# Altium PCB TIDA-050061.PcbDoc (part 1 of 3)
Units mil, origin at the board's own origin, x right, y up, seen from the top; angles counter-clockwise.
Board outline 3950.94 x 4411.21 mil, 8 copper layers (Top Layer, Layer 1, Layer 2, Layer 3, Layer 4, Layer 5, Layer 6, Bottom Layer), stack 61.2 mil thick; 178 components, 34 nets, 398 pads, 112 vias.
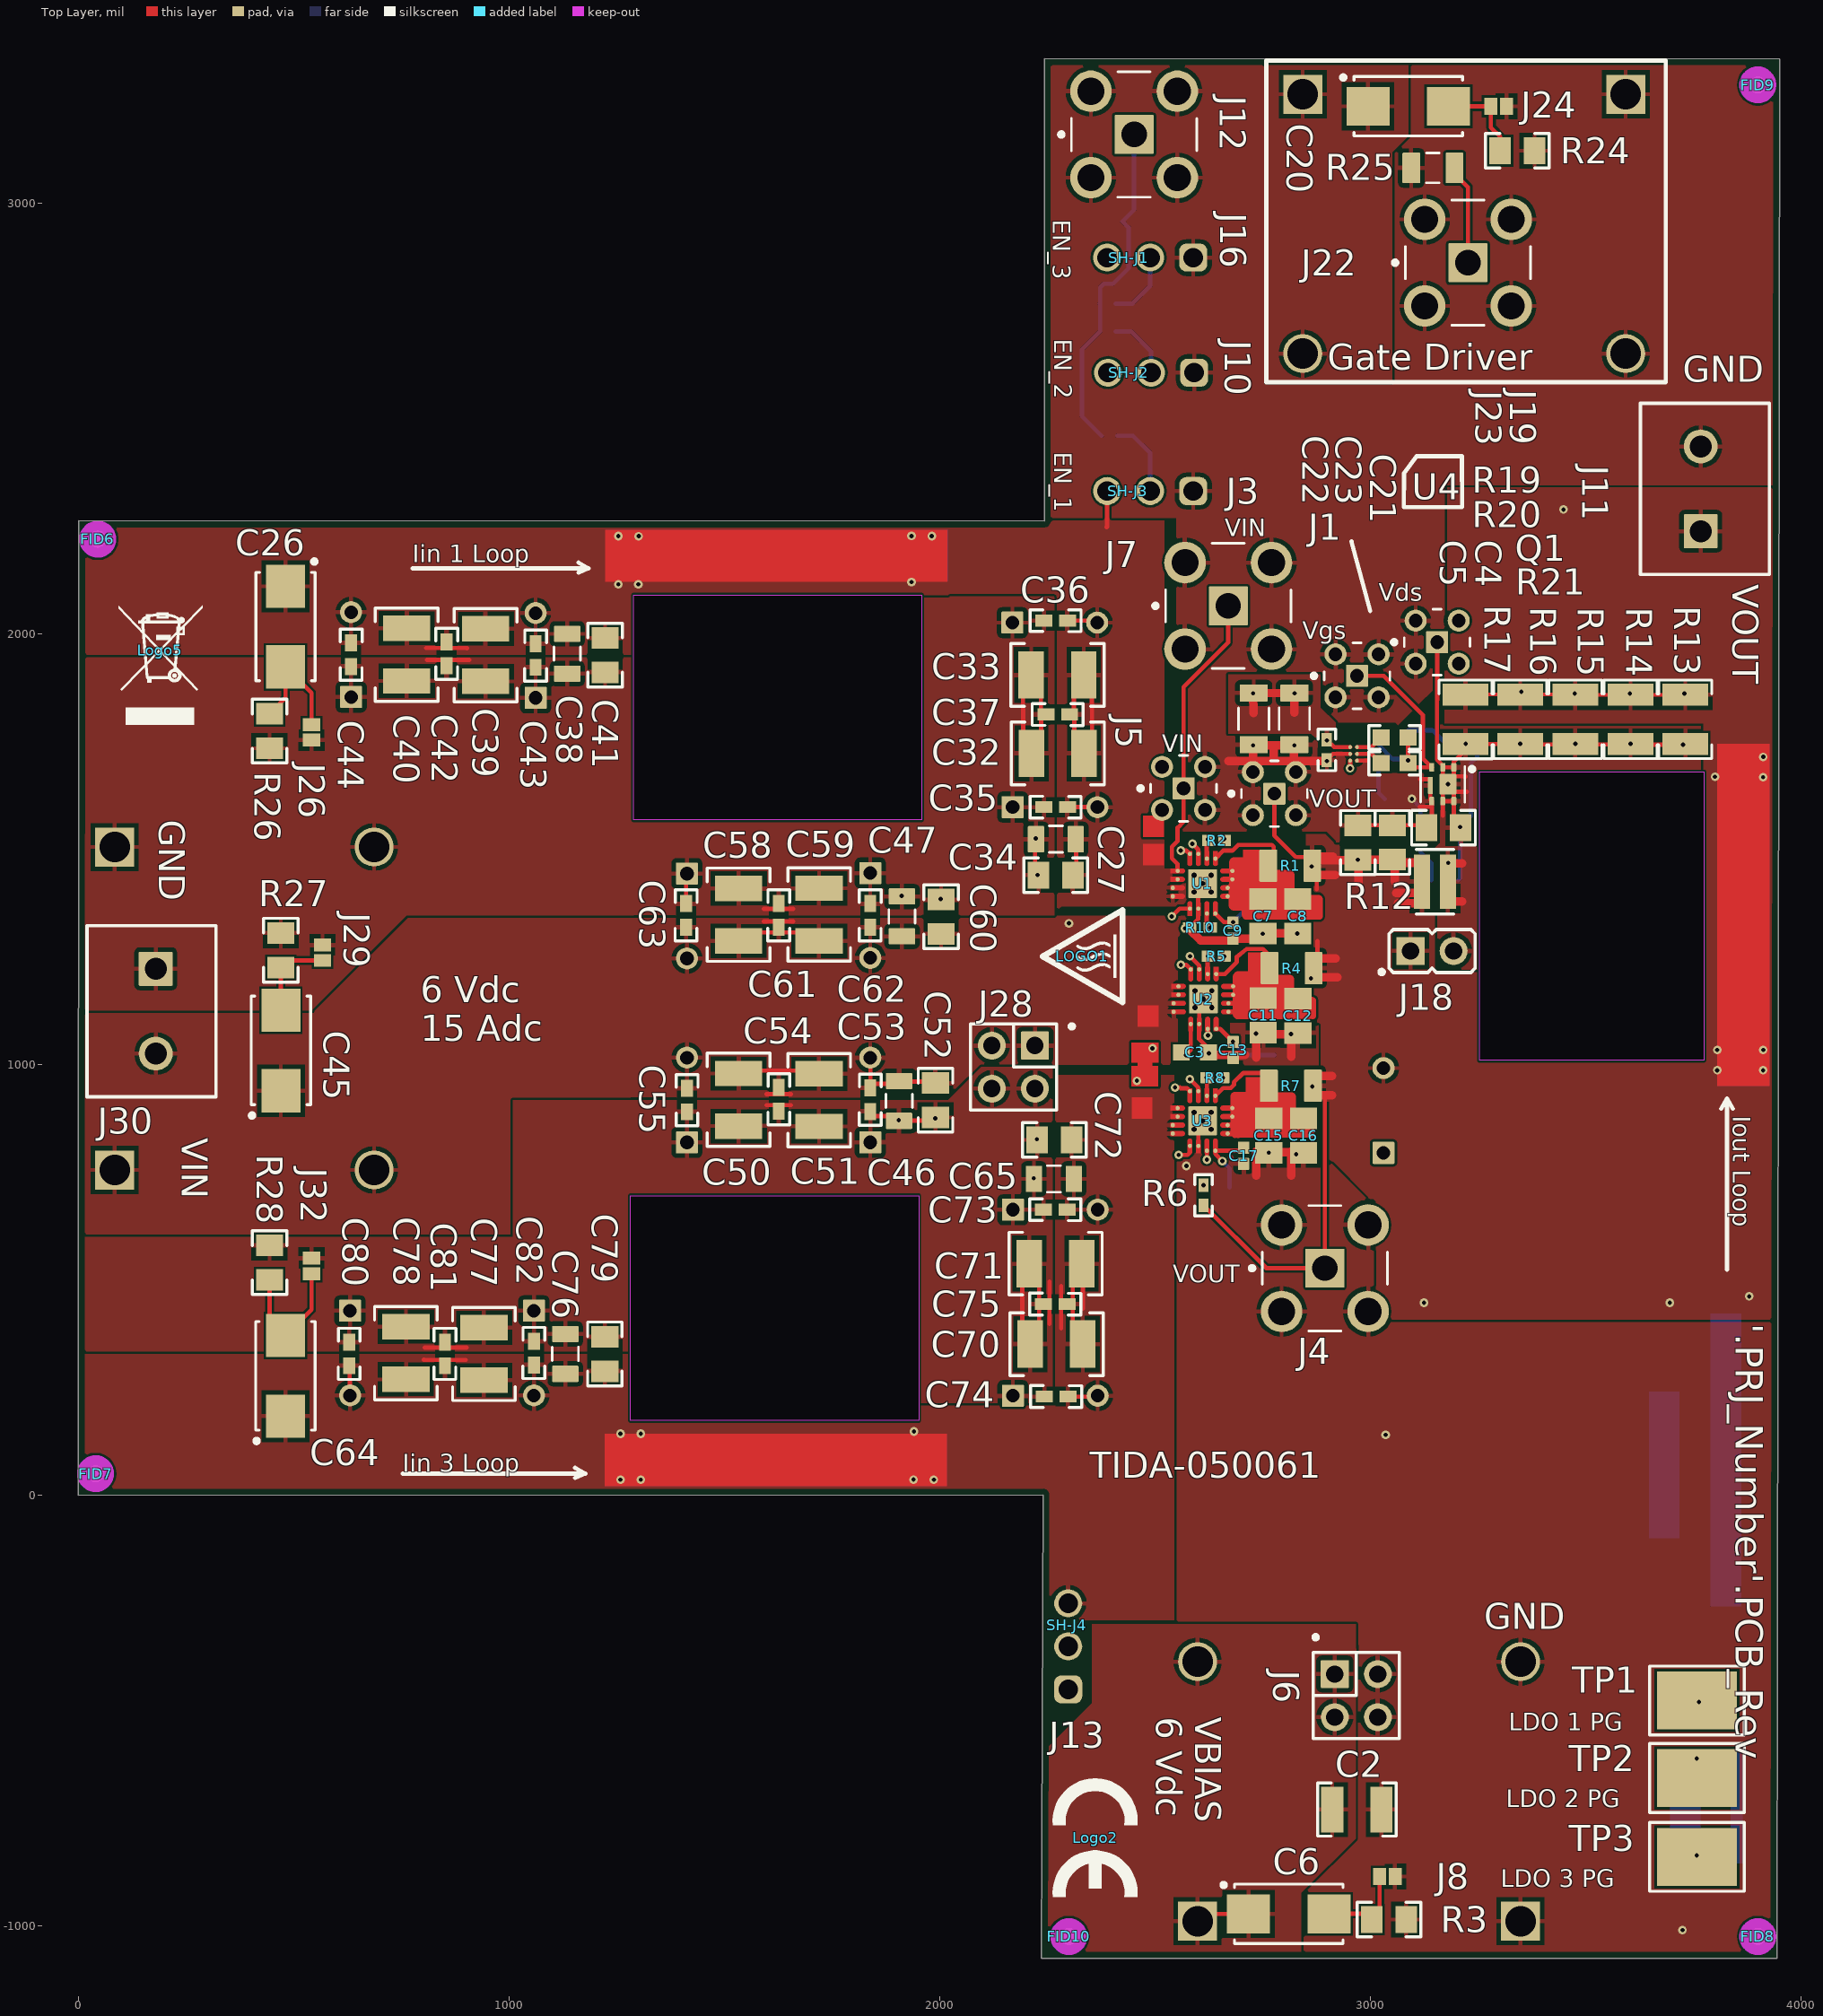
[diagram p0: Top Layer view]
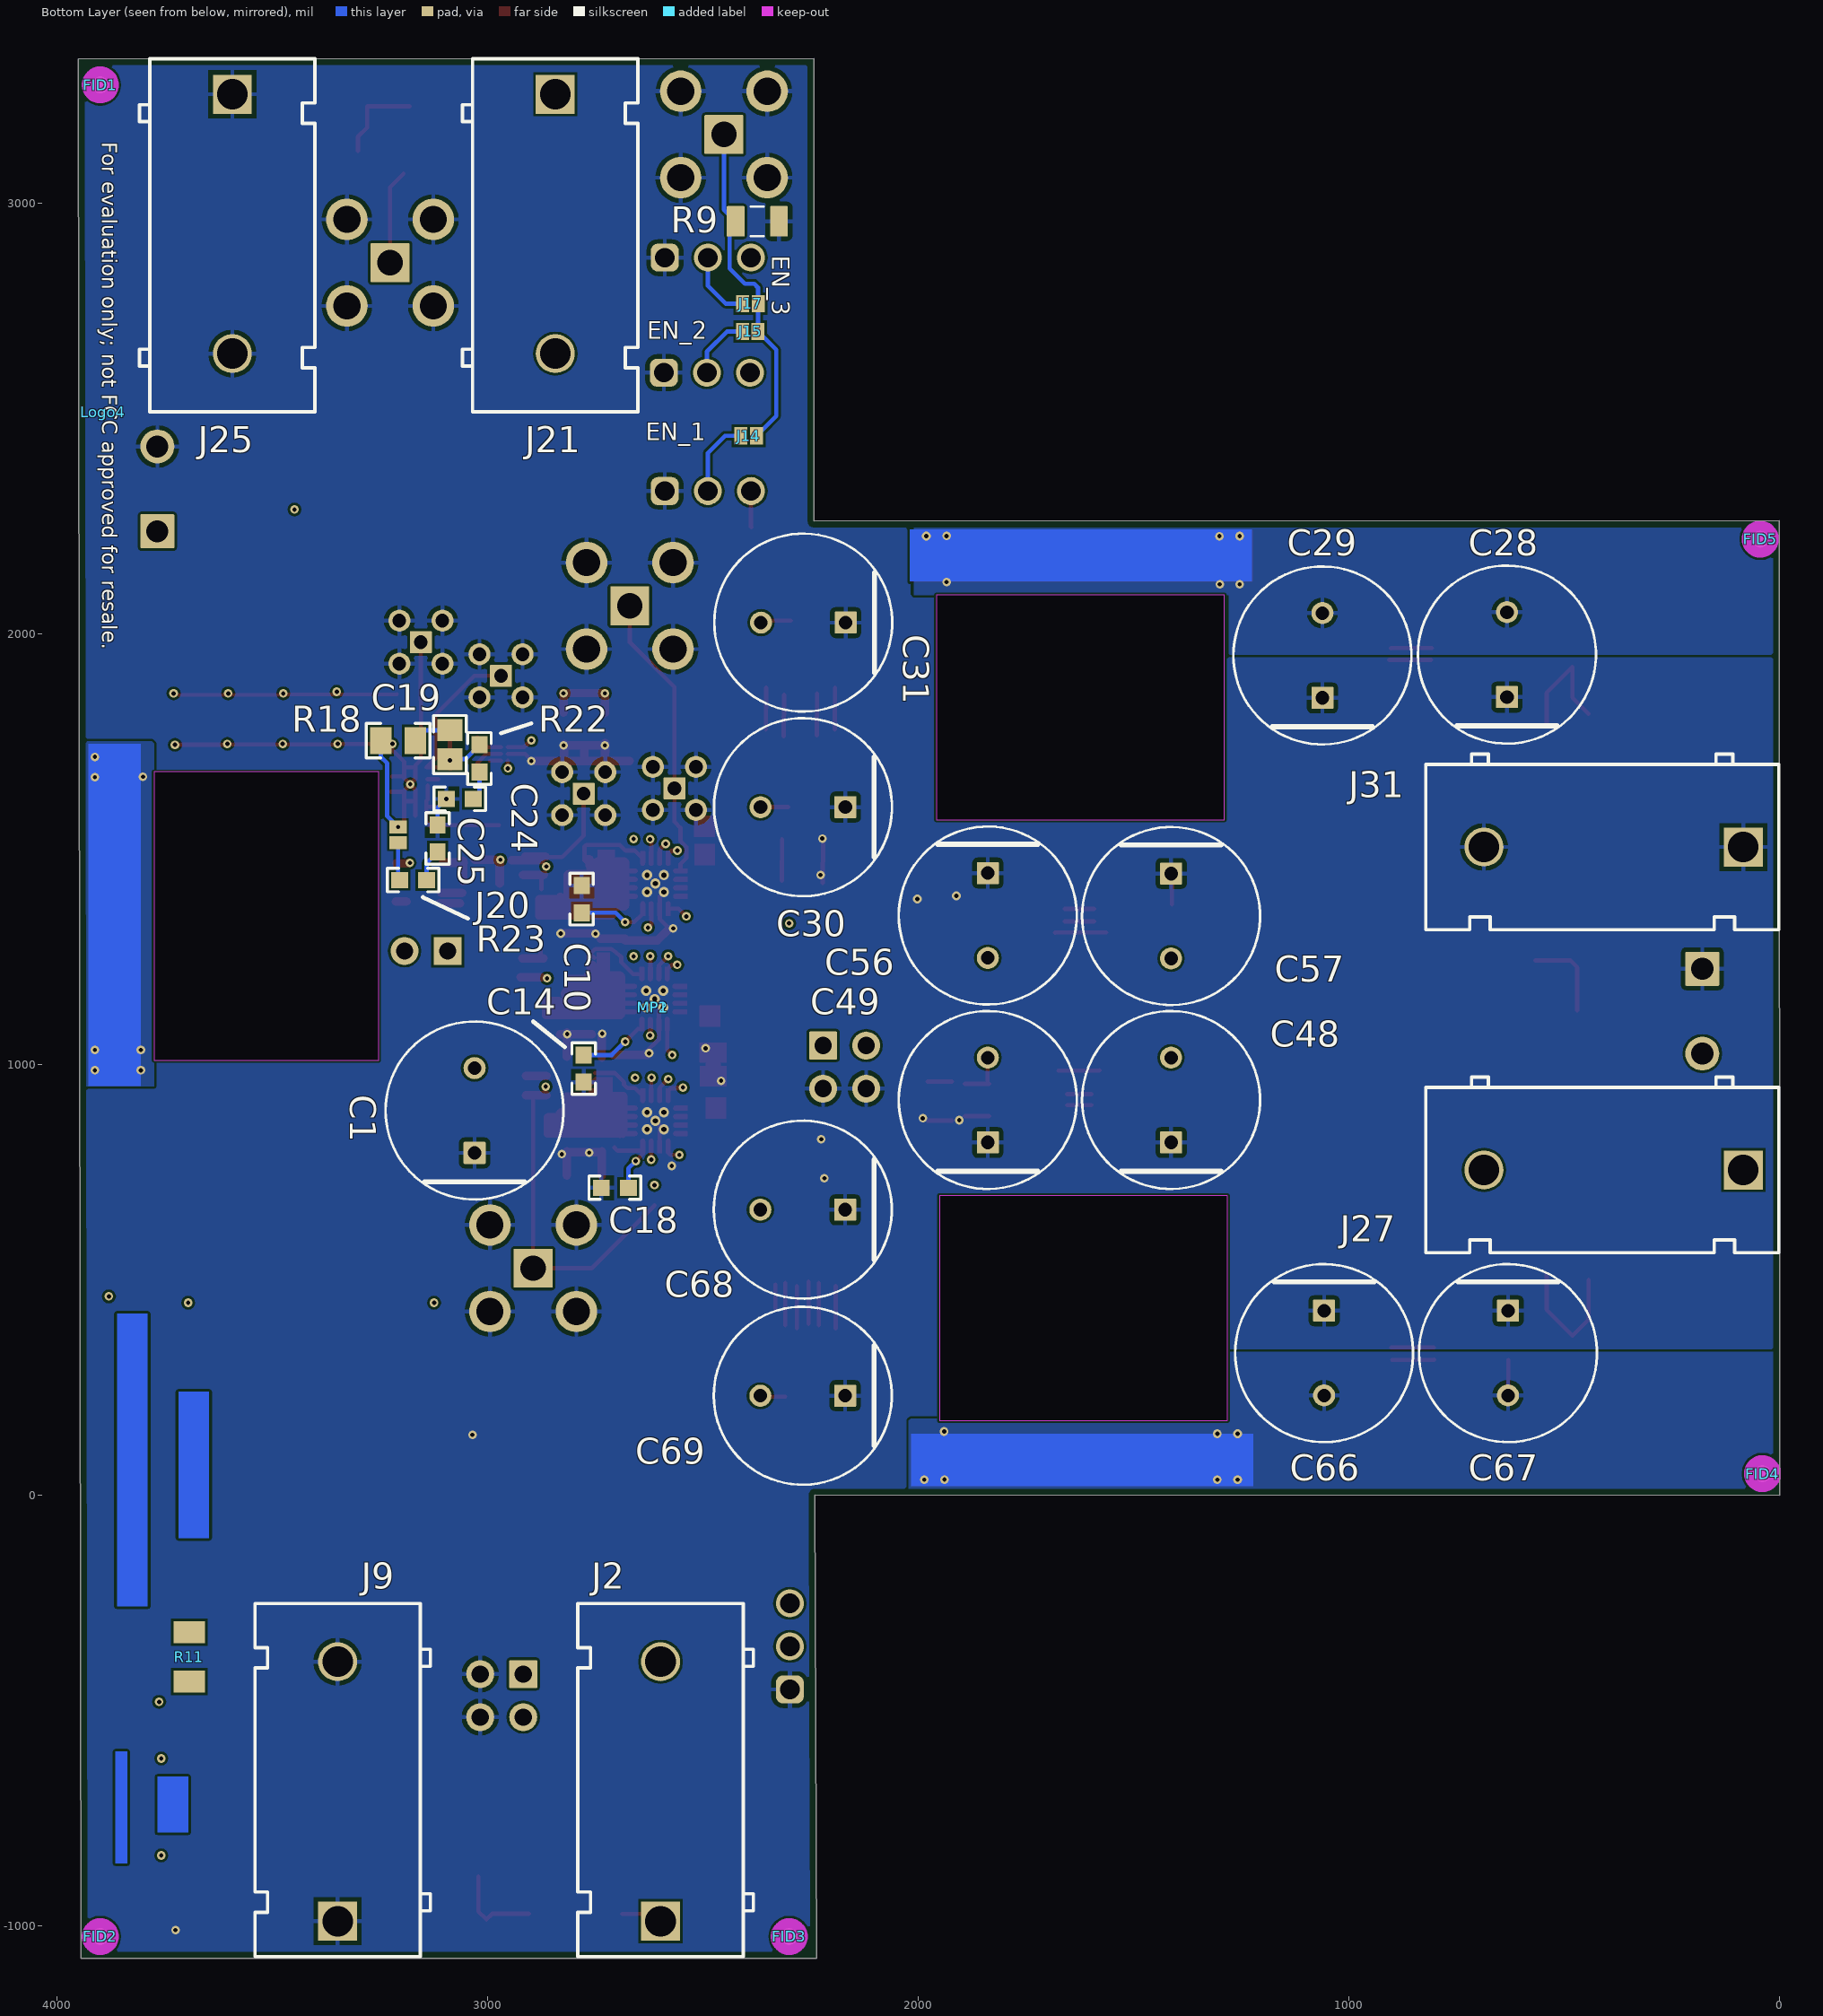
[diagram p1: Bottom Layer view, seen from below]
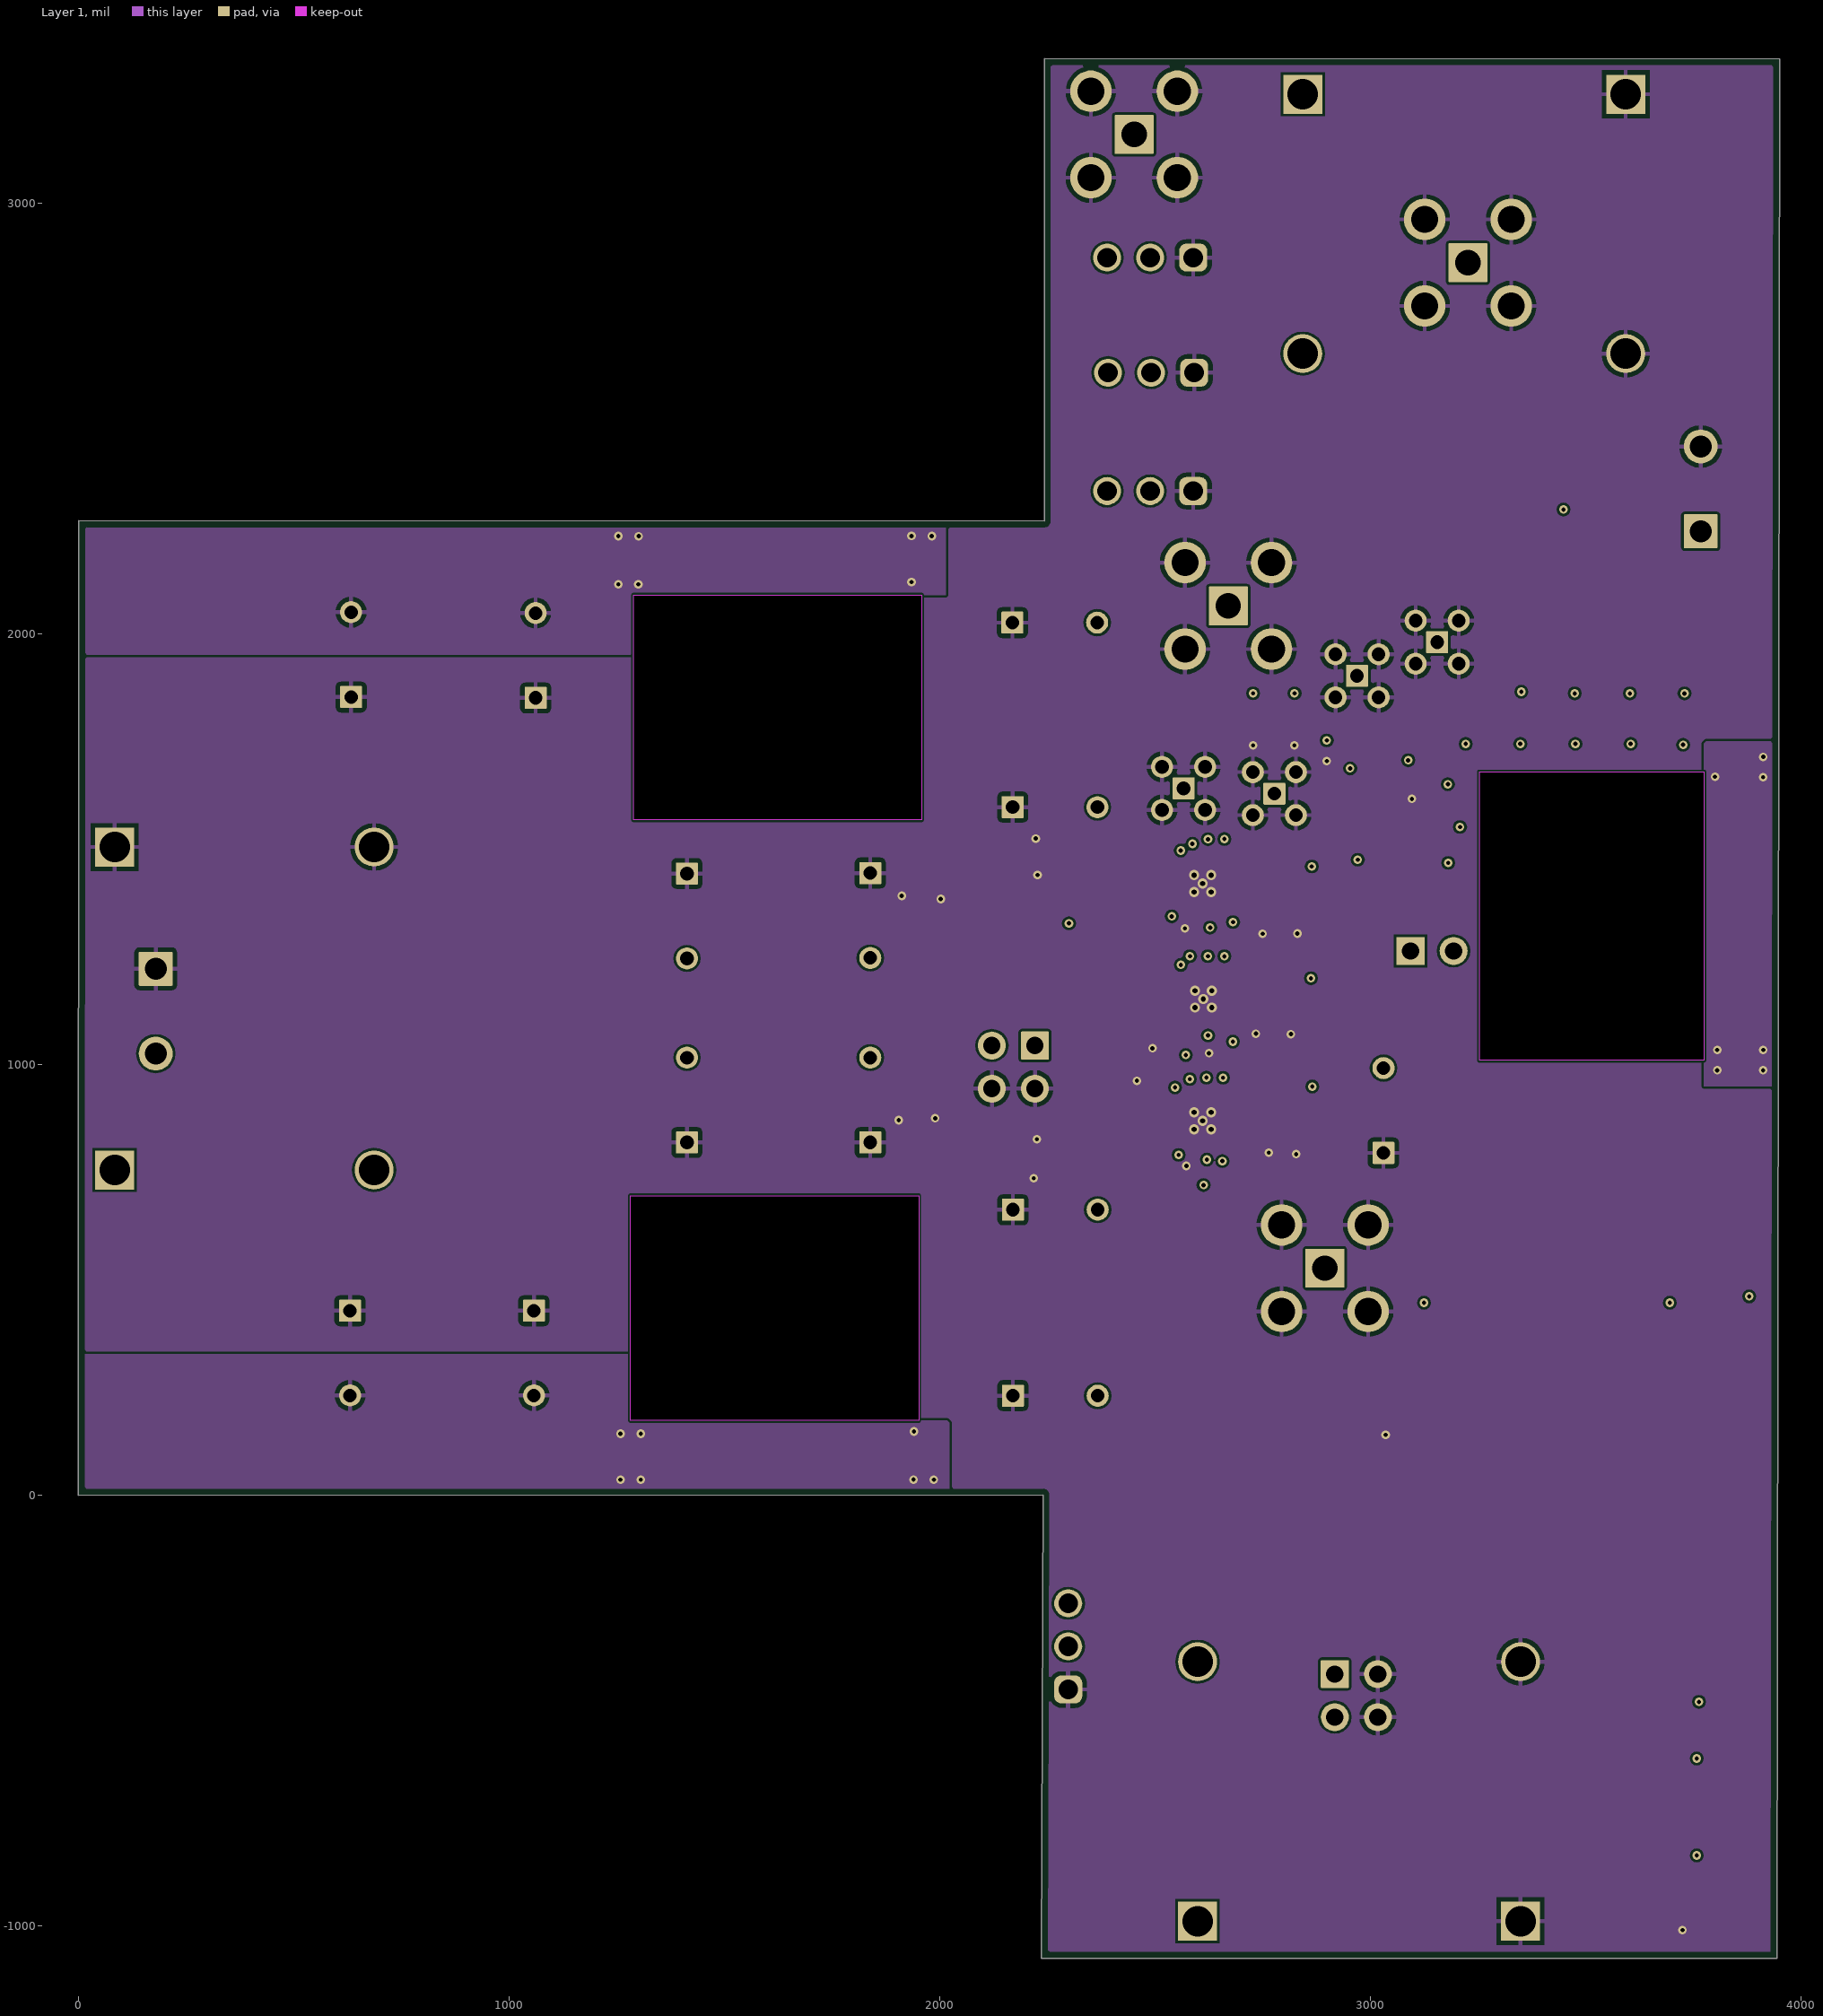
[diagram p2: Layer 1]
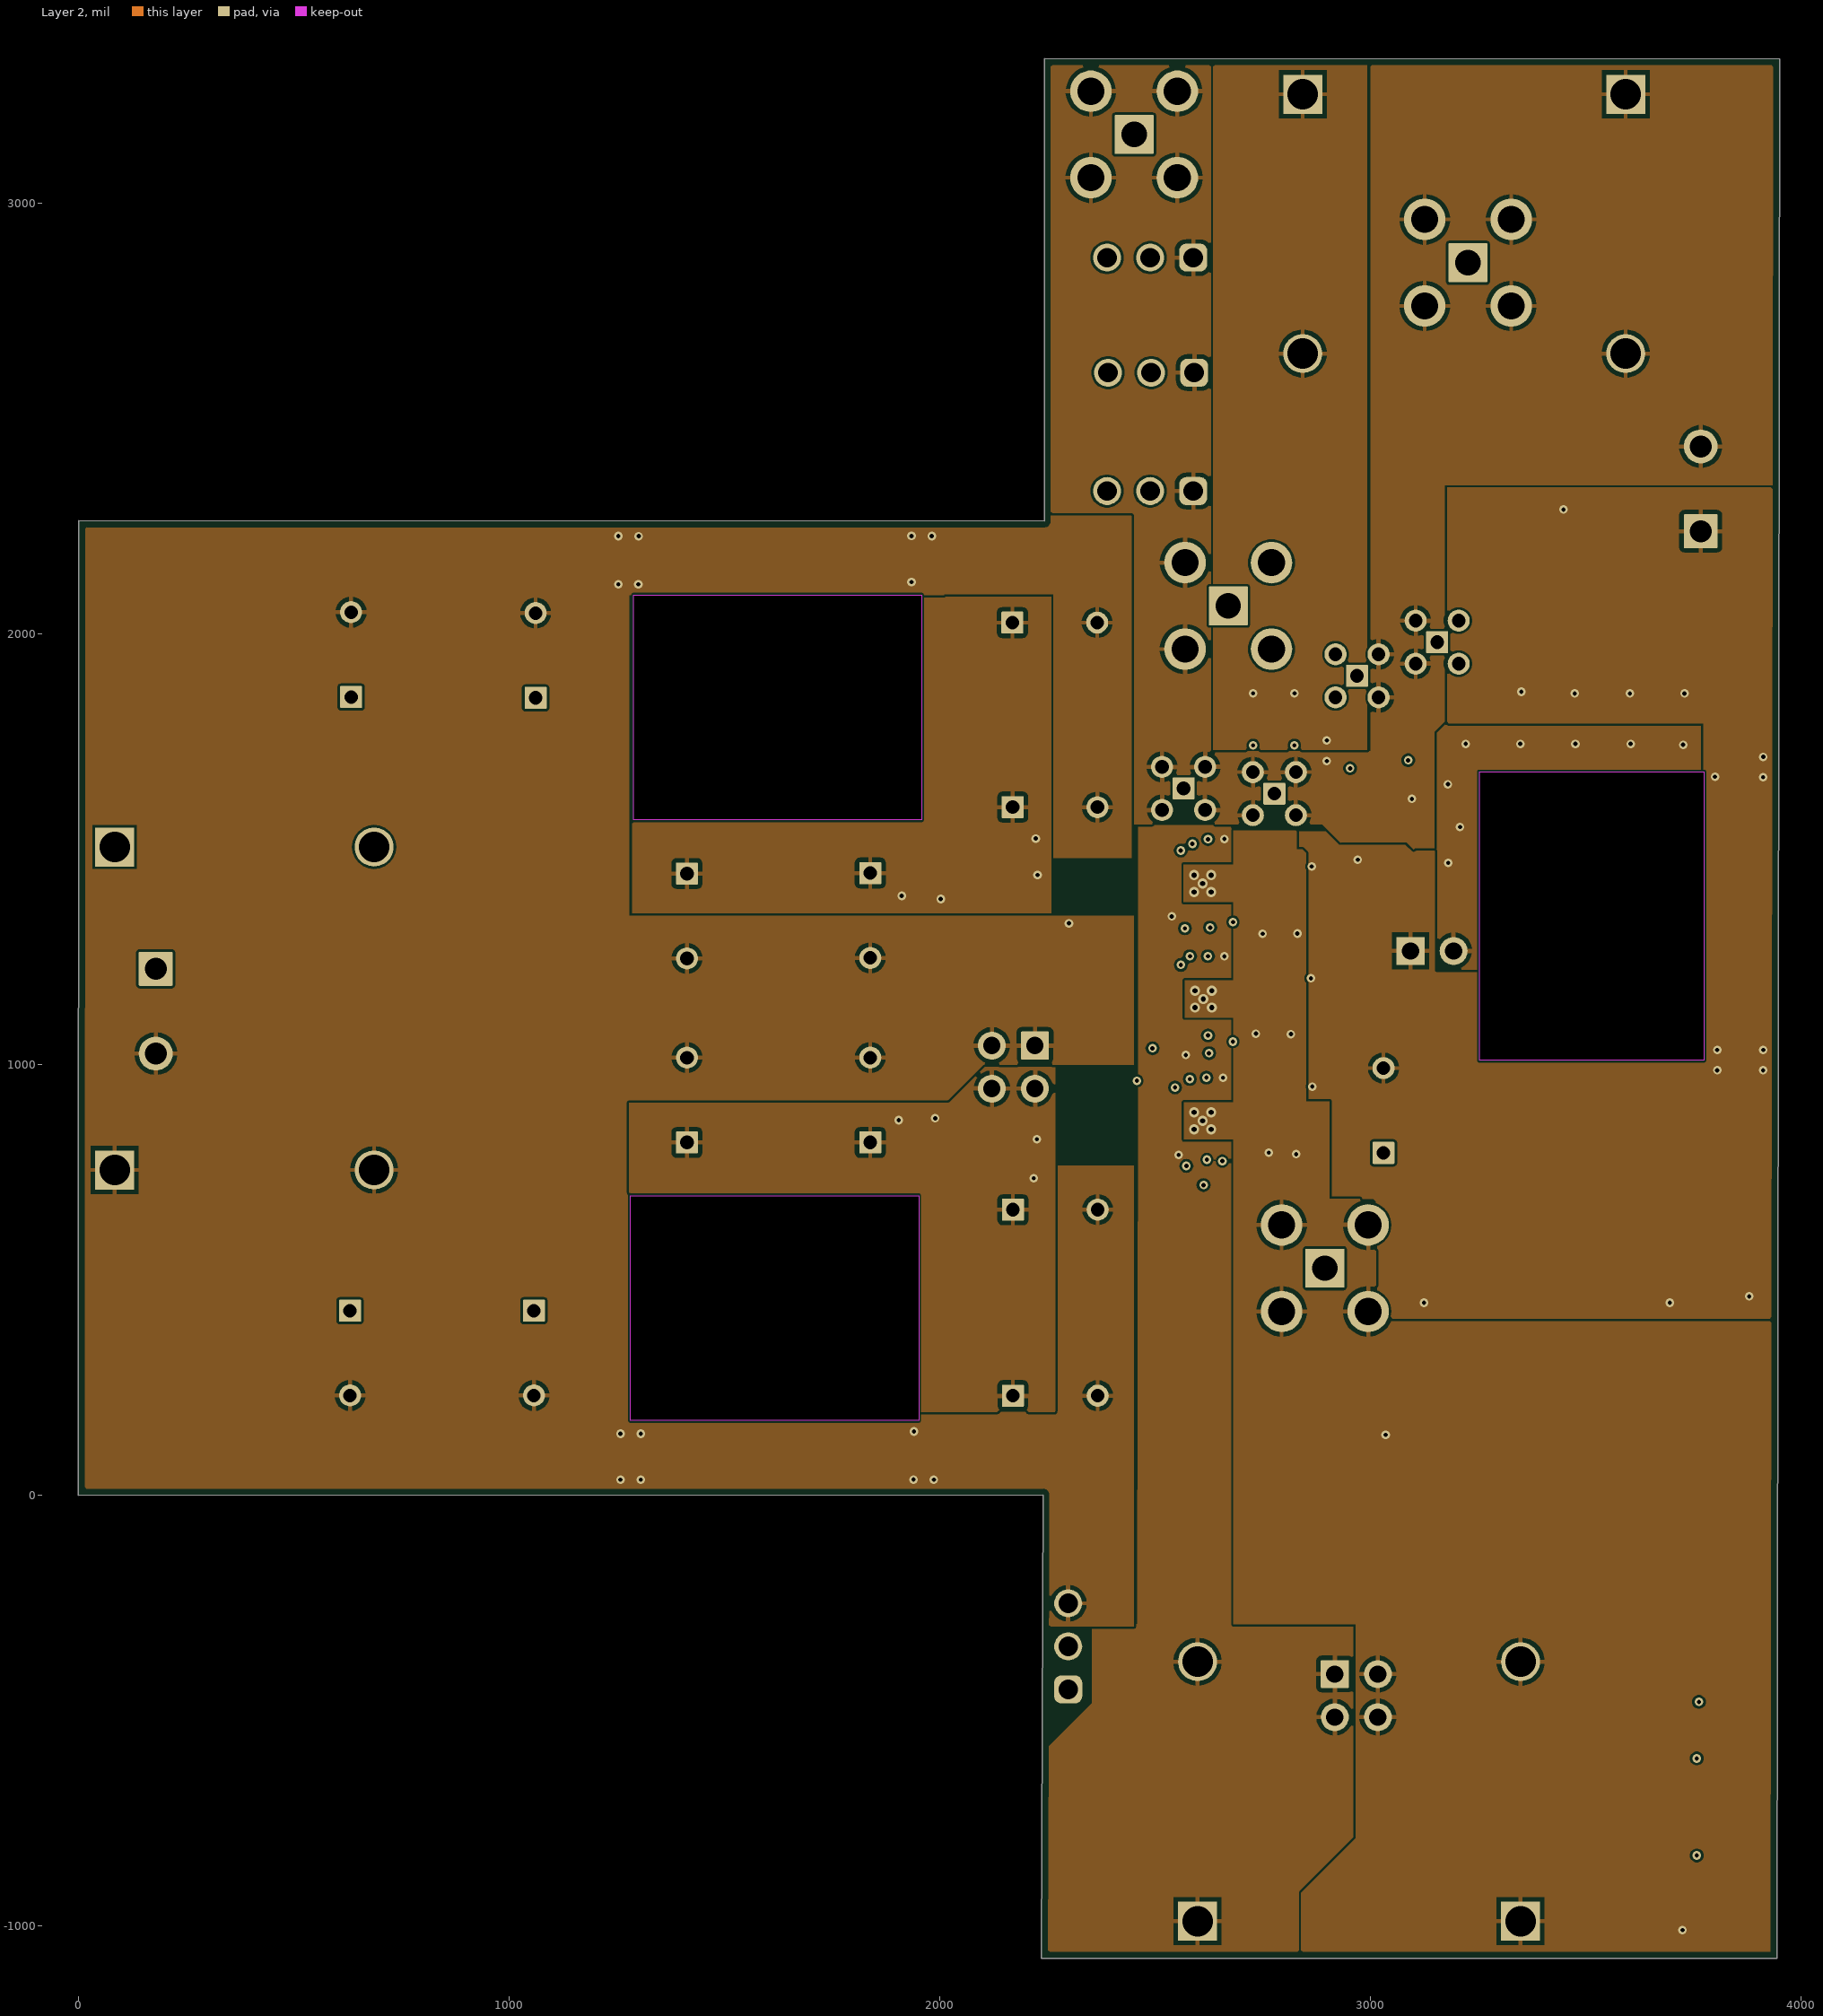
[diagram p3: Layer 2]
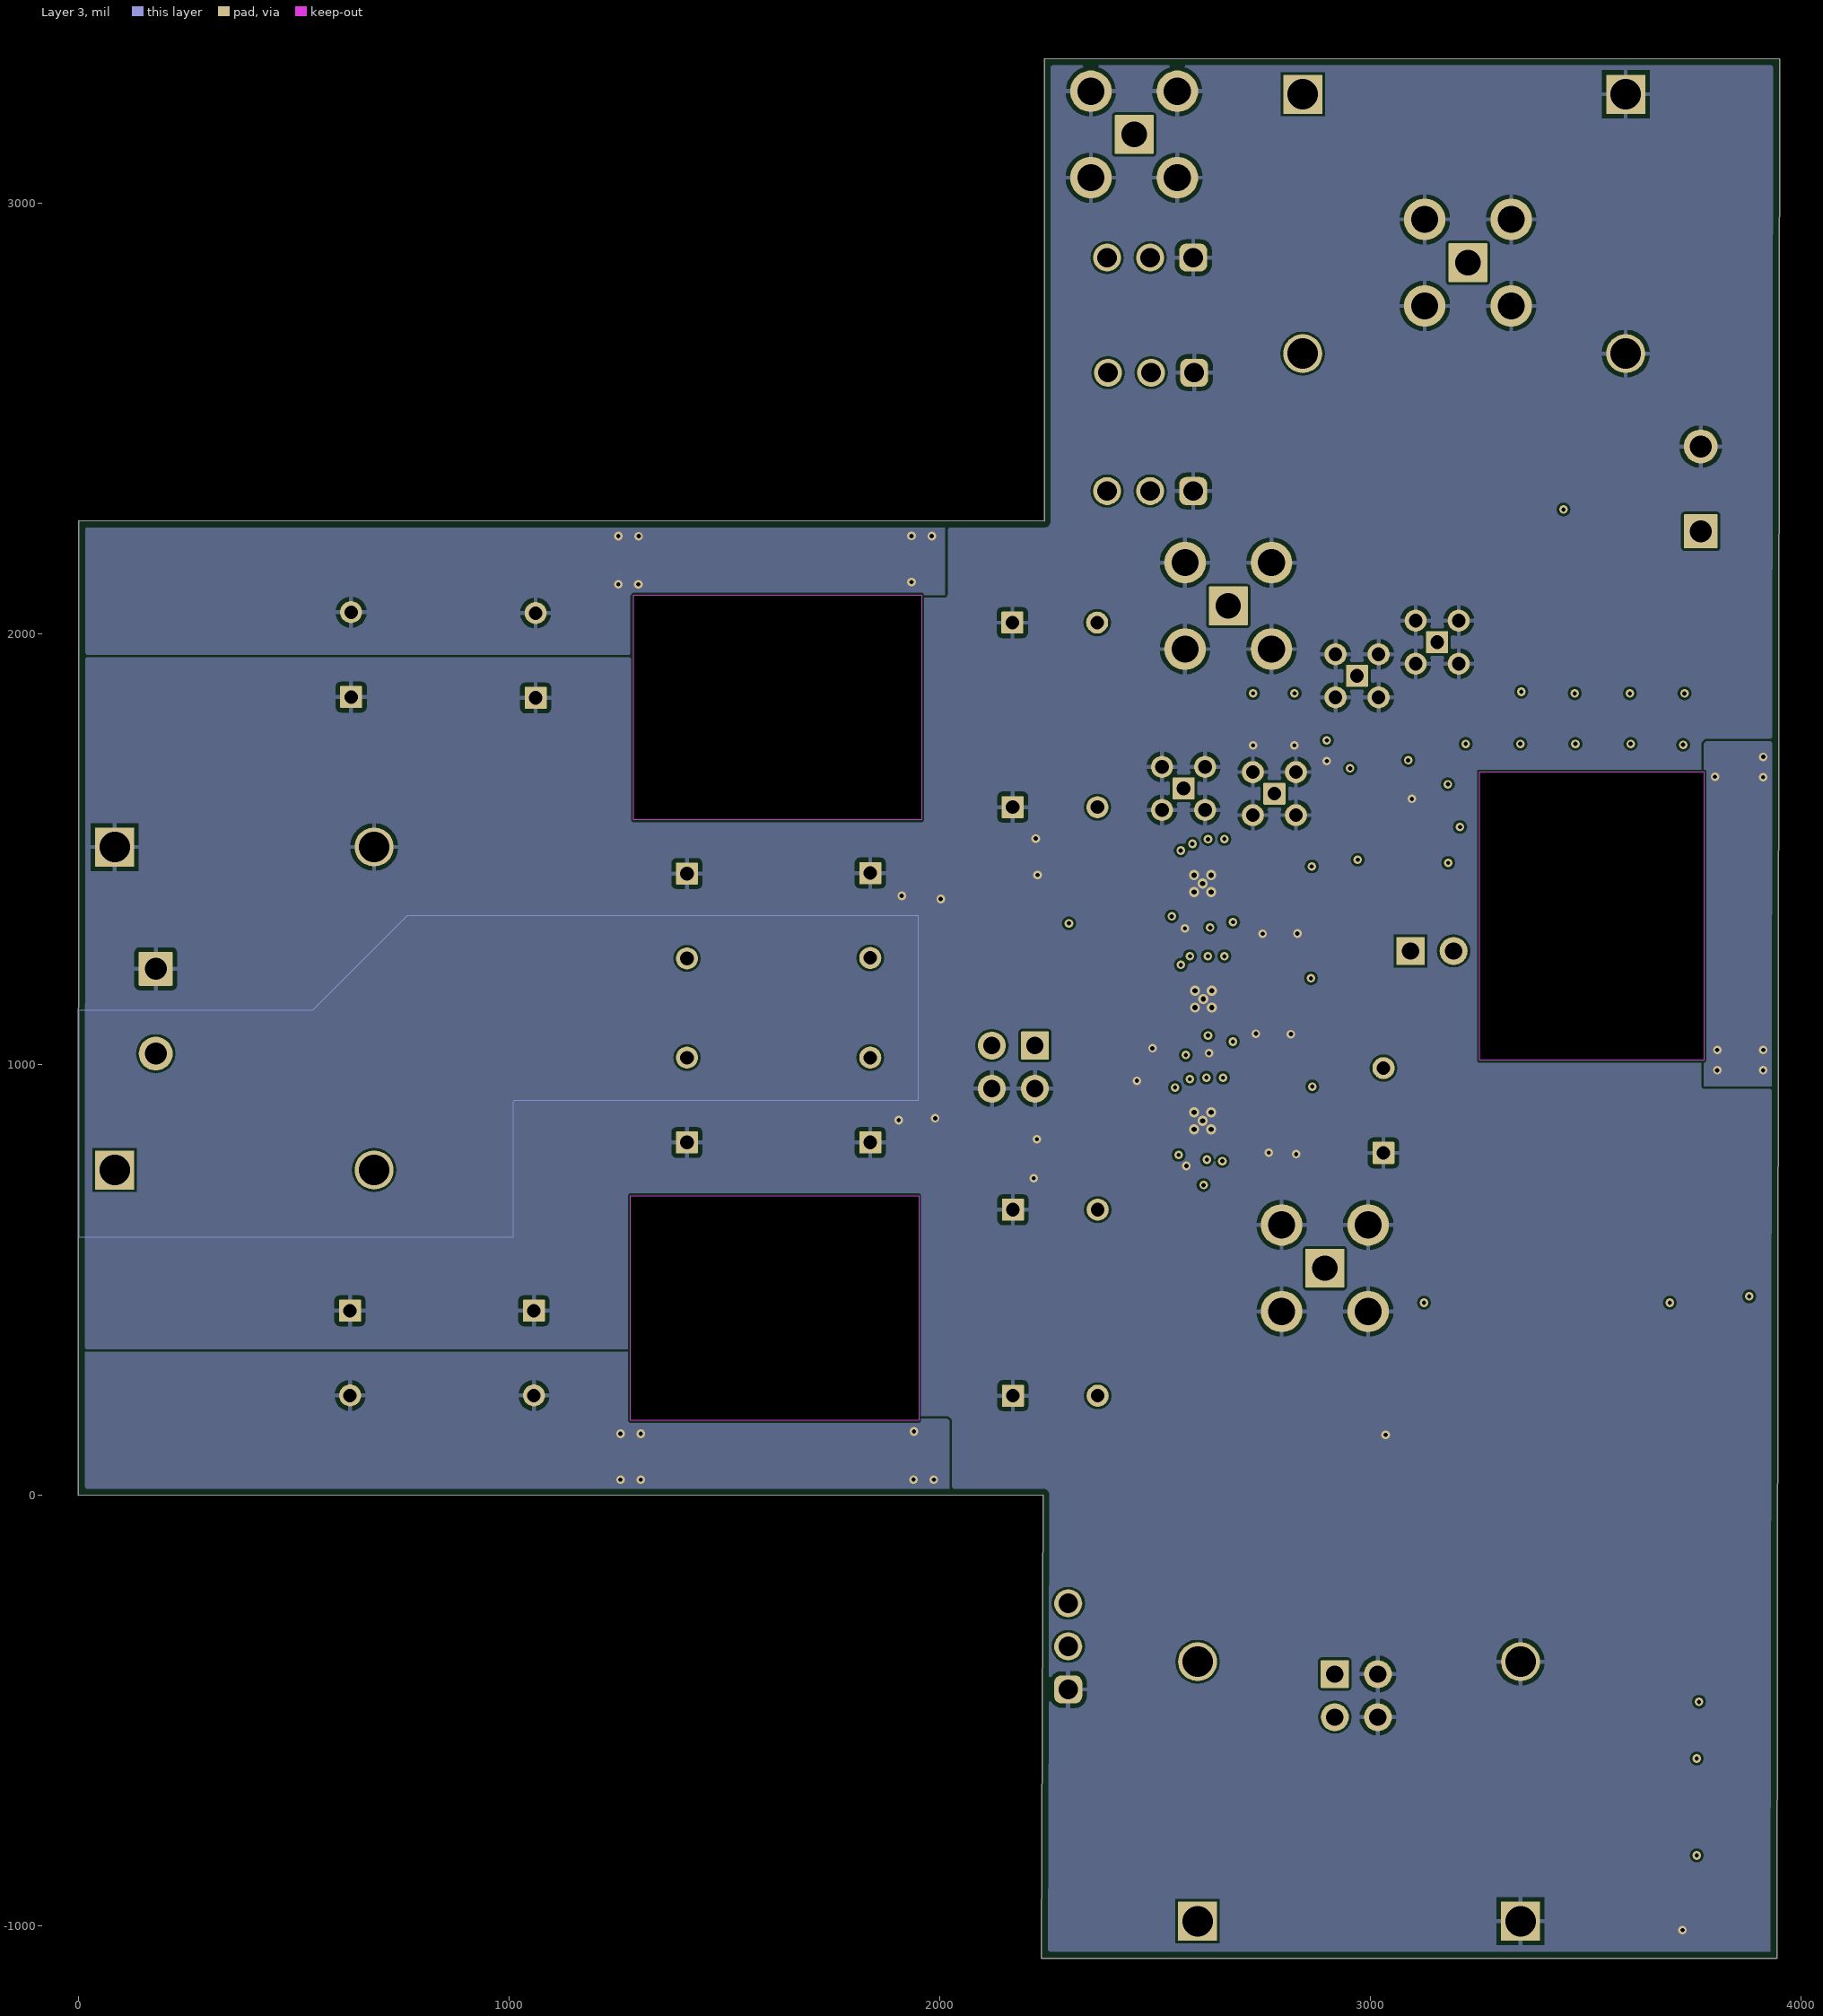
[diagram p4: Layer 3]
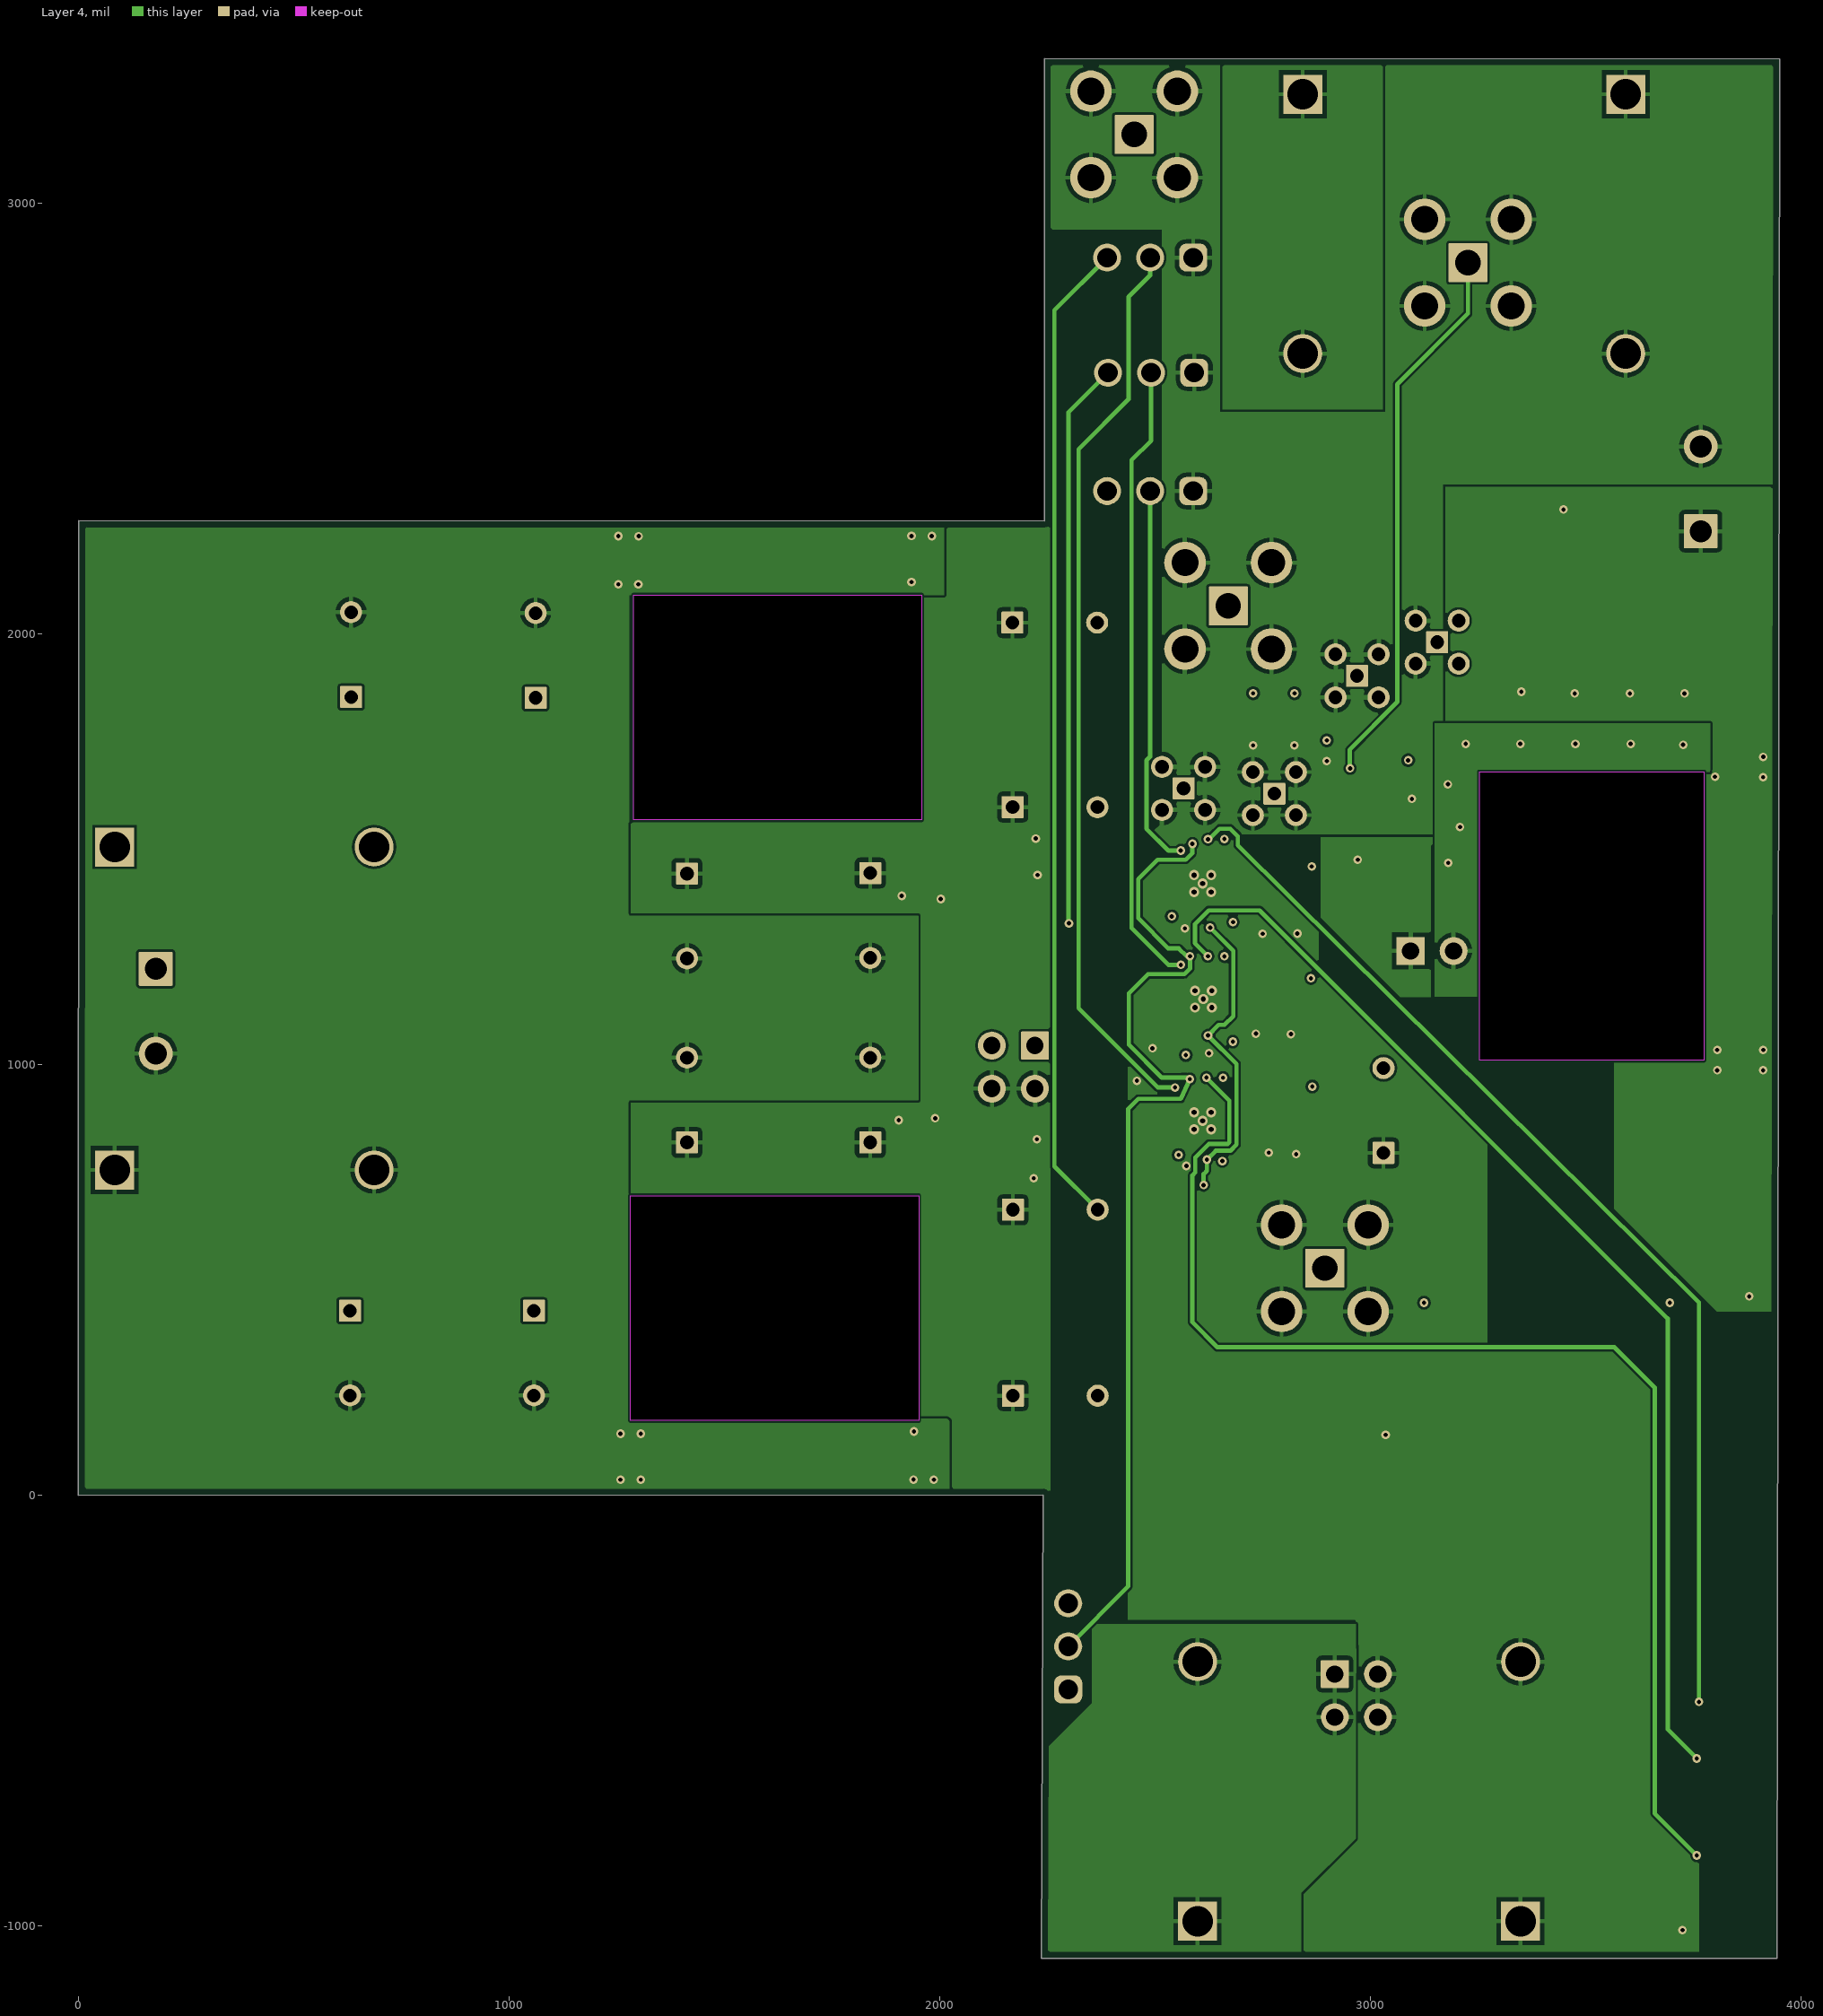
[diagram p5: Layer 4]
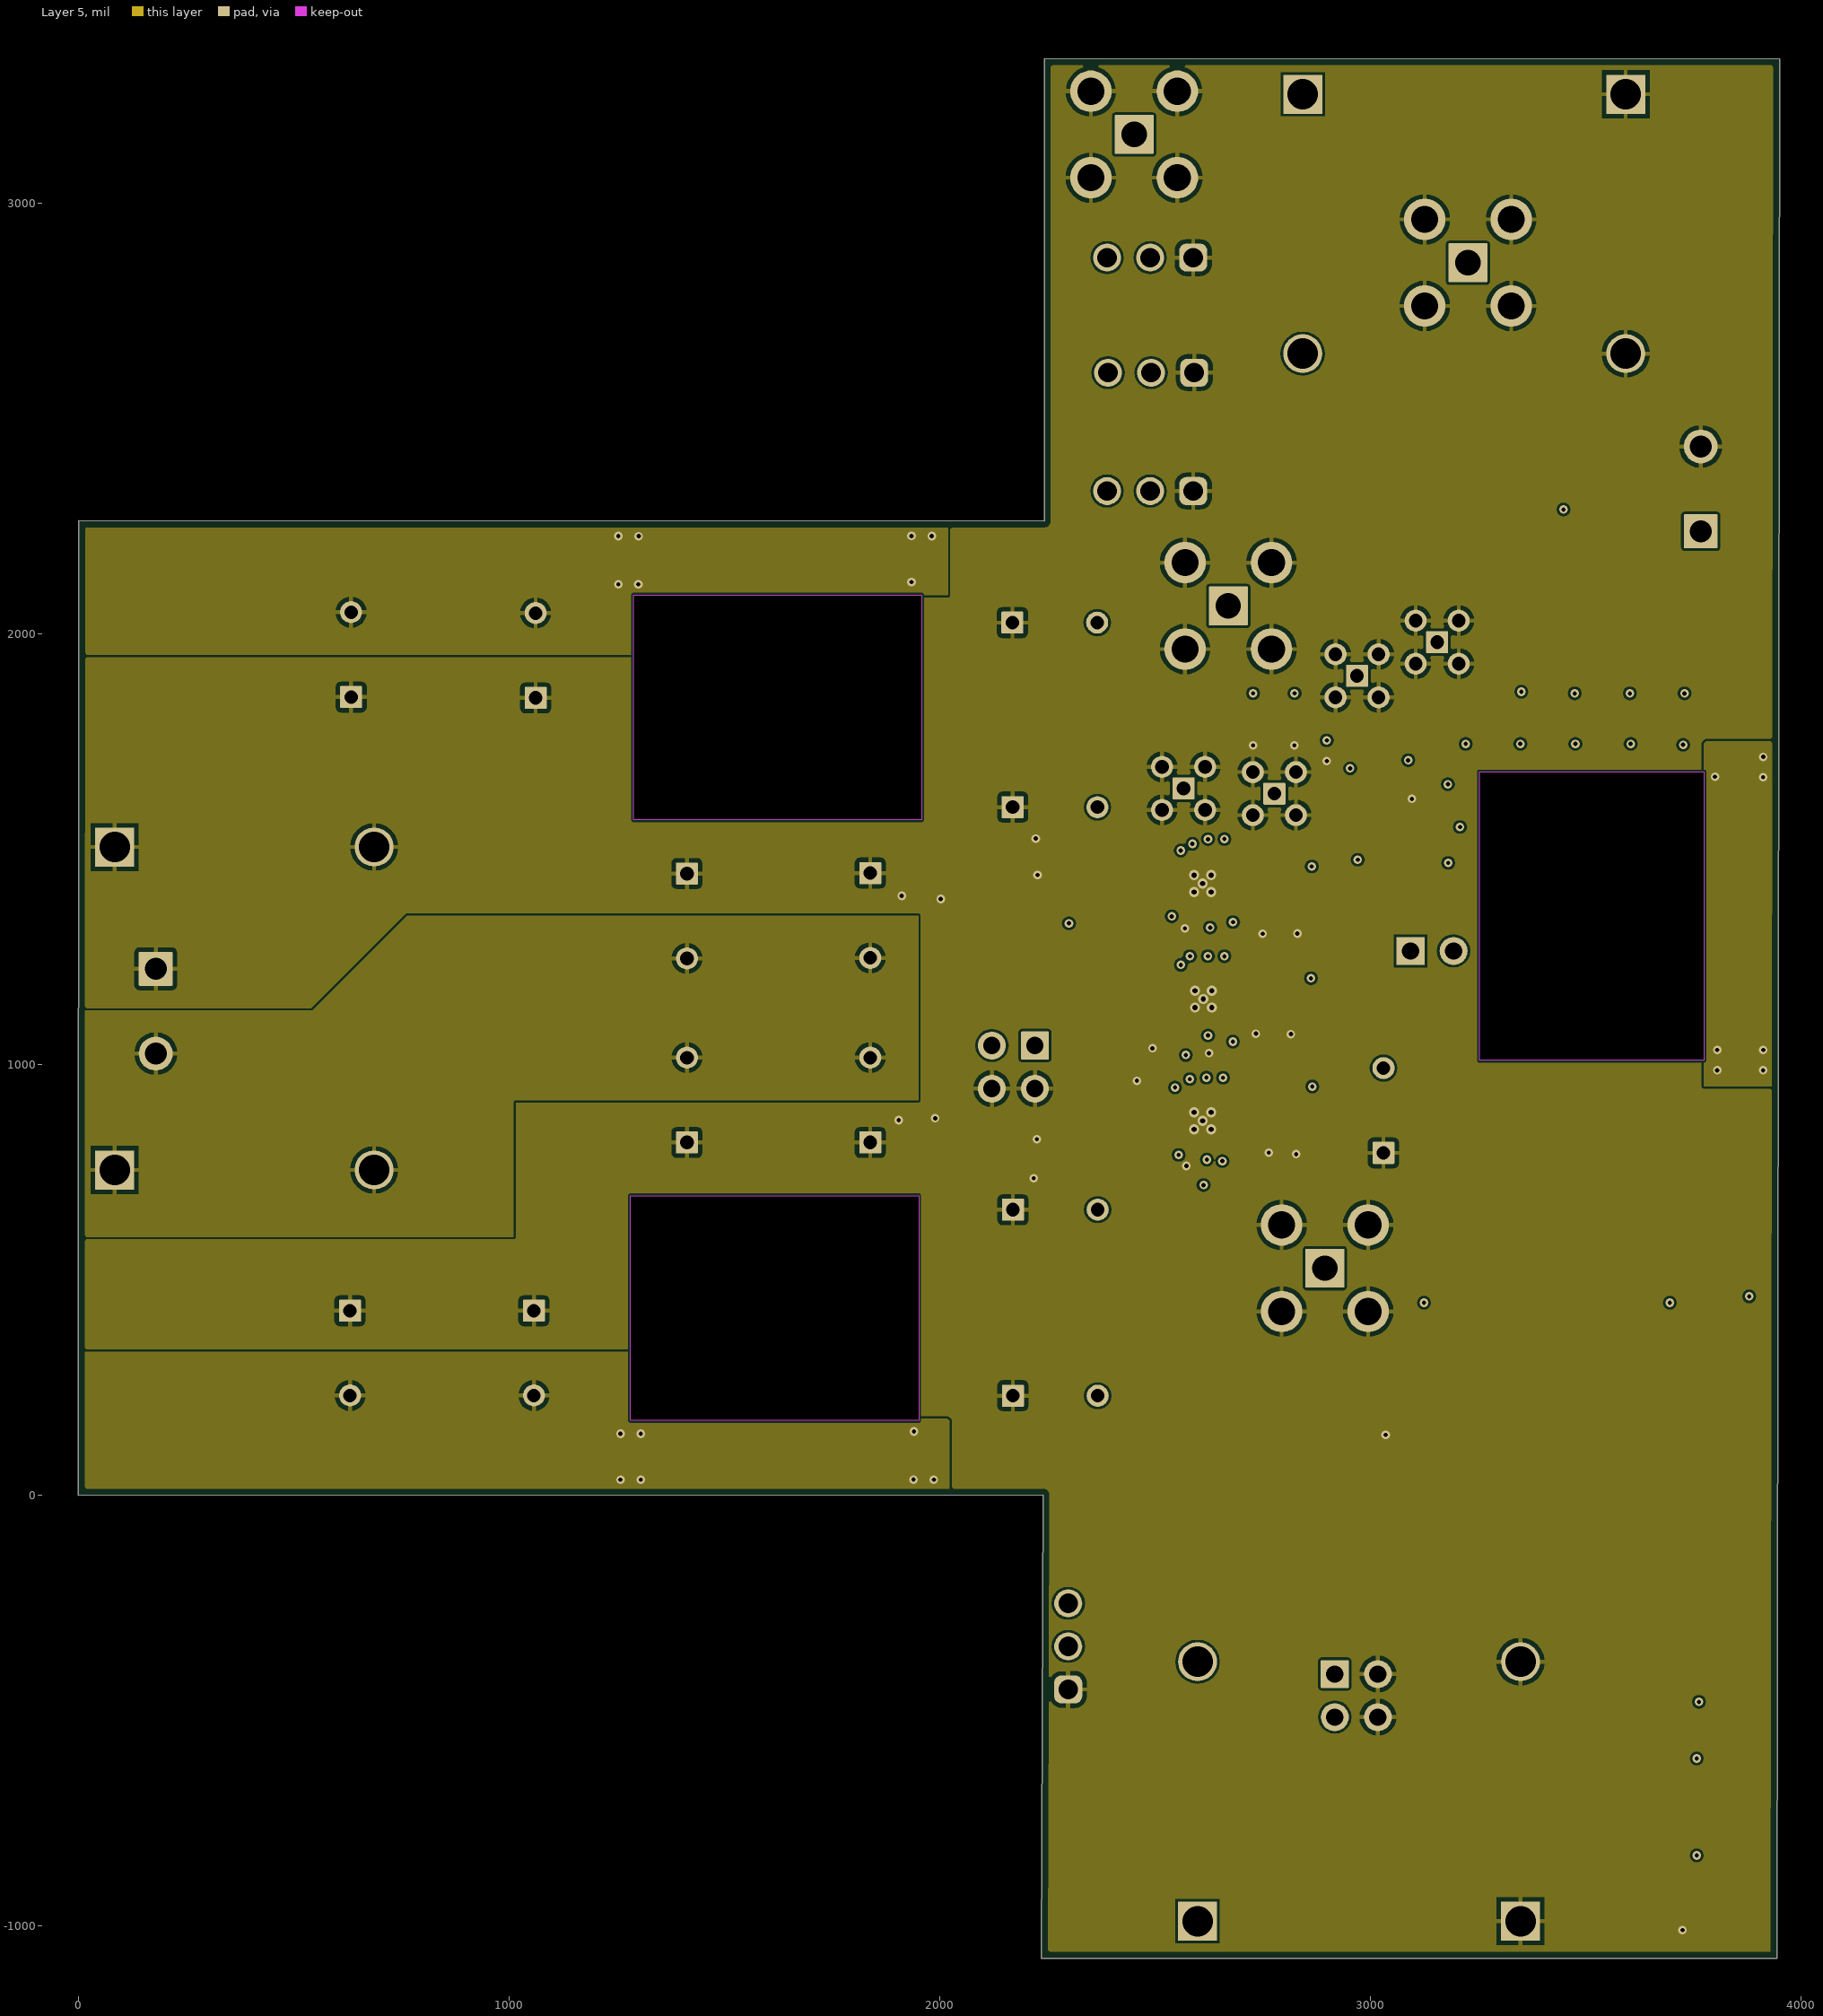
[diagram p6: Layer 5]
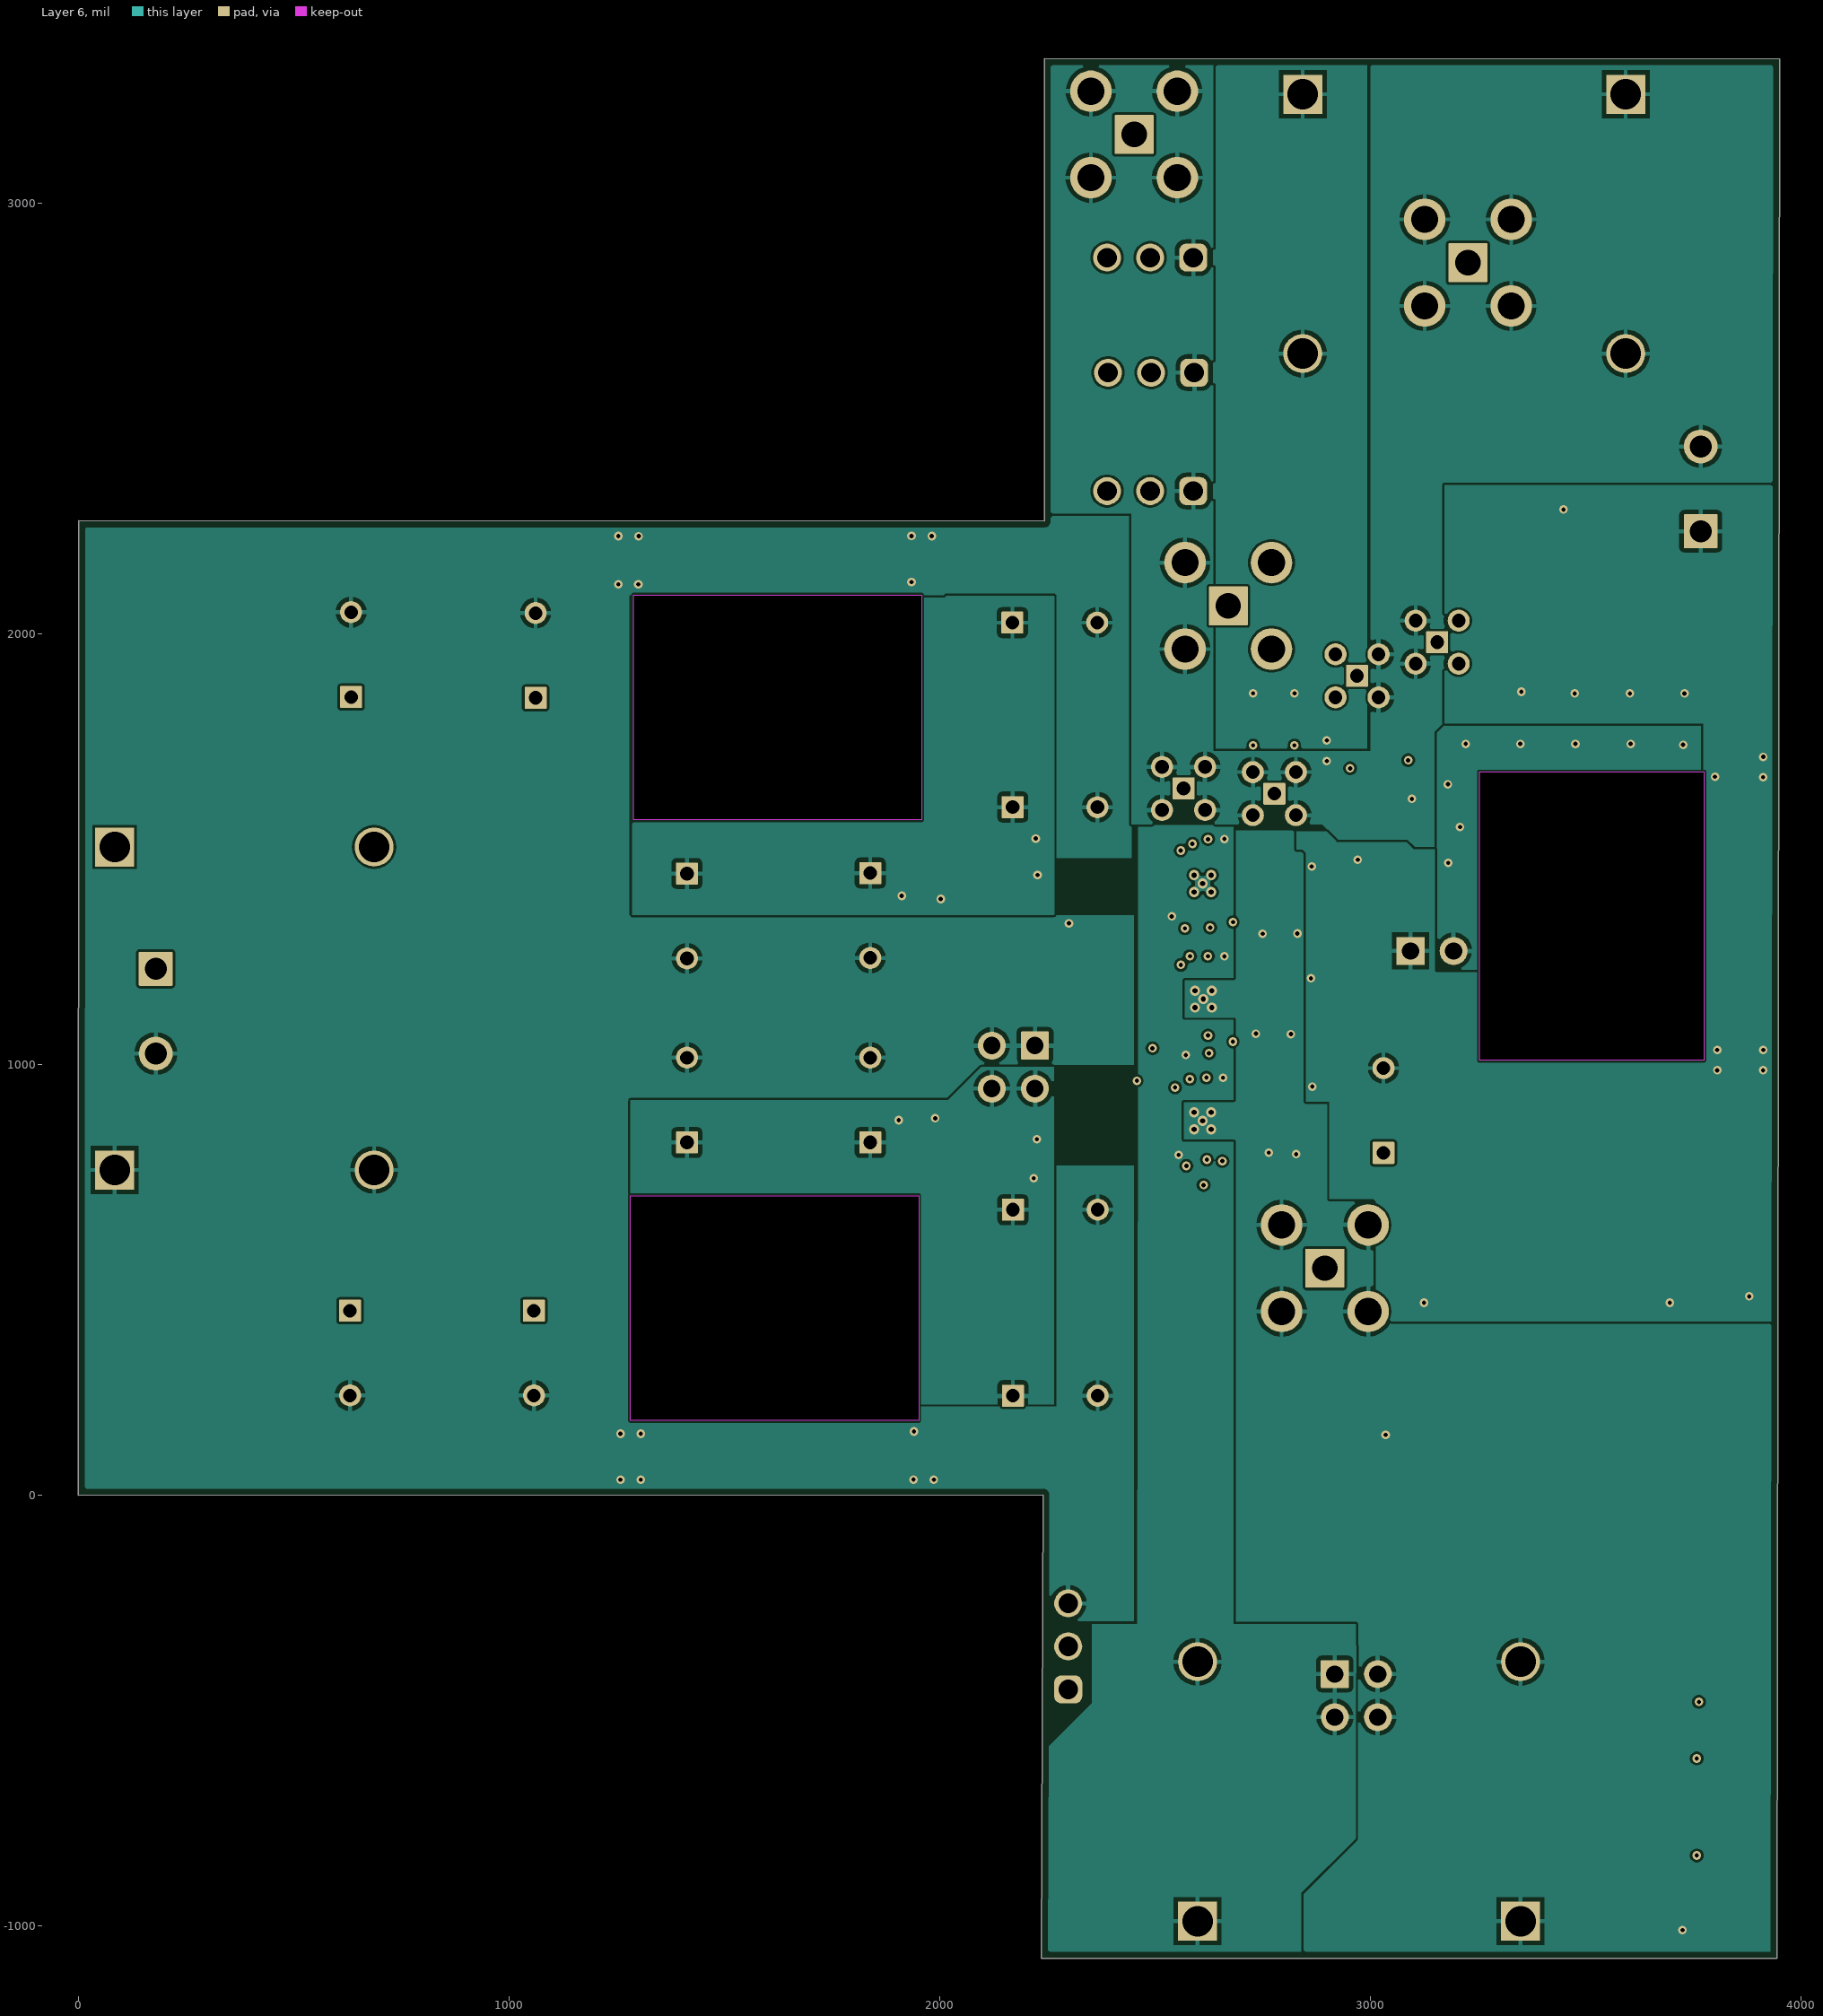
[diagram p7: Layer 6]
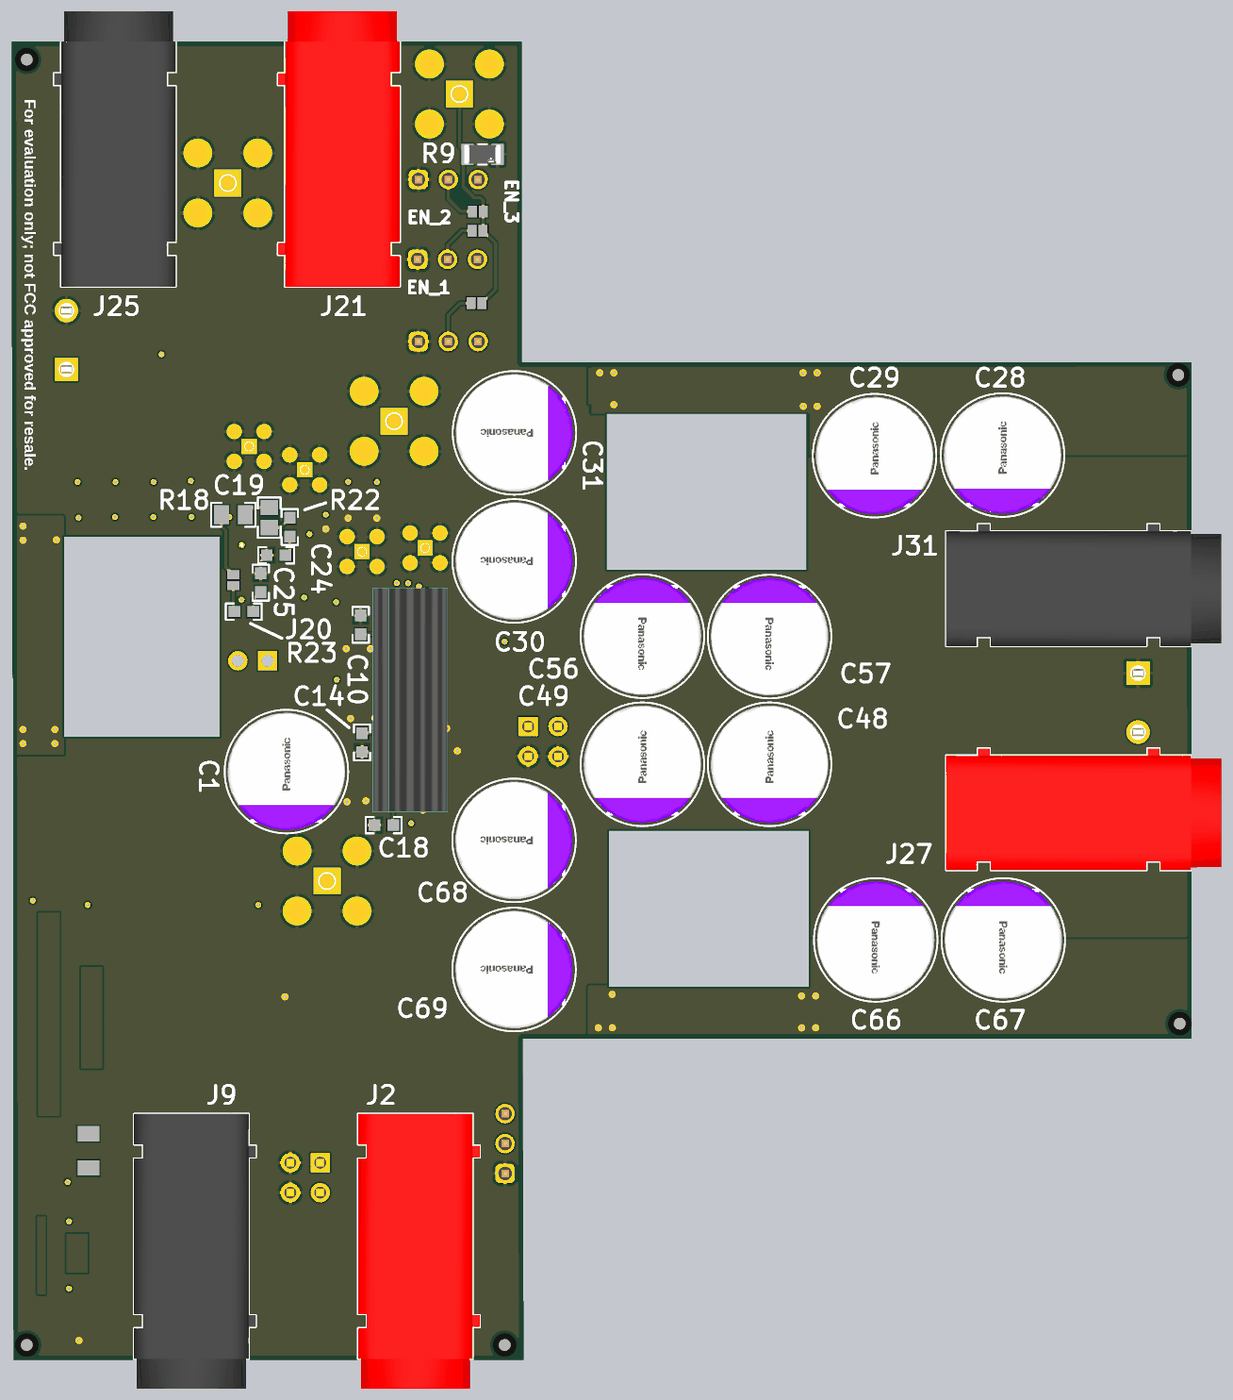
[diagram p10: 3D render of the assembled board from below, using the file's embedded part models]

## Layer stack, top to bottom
Top Solder: solder mask 0.4, Solder Resist, Dk 3.5
Top Layer: signal copper 1.378
Dielectric 1: prepreg 7.168, PP-006, Dk 4.1
Layer 1: signal copper 1.378
Dielectric 2: prepreg 7.168, PP-006, Dk 4.1
Layer 2: signal copper 1.378
Dielectric 3: prepreg 7.168, PP-006, Dk 4.1
Layer 3: signal copper 1.378
Dielectric 4: core 7.168, FR-4, Dk 4.8
Layer 4: signal copper 1.378
Dielectric 5: prepreg 7.168, PP-006, Dk 4.1
Layer 5: signal copper 1.378
Dielectric 6: prepreg 7.168, PP-006, Dk 4.1
Layer 6: signal copper 1.378
Dielectric 7: prepreg 7.168, PP-006, Dk 4.1
Bottom Layer: signal copper 1.378
Bottom Solder: solder mask 0.4, Solder Resist, Dk 3.5

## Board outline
0,0 2240.16,0.35 2236.81,-1070.97 2236.81,-1075.32 3944.58,-1075.28 3950.94,3335.56 2243.17,3335.89 2243.13,2261.93 0.8,2262.93
cut-out: 3253.64,1679.33 3775.3,1679.33 3775.3,1010.04 3253.64,1010.04
cut-out: 1289.22,1568.21 1289.22,2089.86 1958.51,2089.86 1958.51,1568.21
cut-out: 1951.48,695.05 1951.48,173.4 1282.19,173.4 1282.19,695.05

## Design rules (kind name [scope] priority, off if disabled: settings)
AcuteAngle [All] p1: minimum=4.50000000000000E+0001 checktracksonly=FALSE
AssemblyTestPointUsage [All] p1: valid=2
BoardOutlineClearance BoardOutlineClearance_MountingHoles [OnCopper and InComponentClass('Mounting Holes')] p1: gap=40 ignorepadtopadclearanceinfootprint=FALSE
BoardOutlineClearance BoardOutlineClearance_Poly [OnCopper and IsPoly] p2: gap=15 ignorepadtopadclearanceinfootprint=FALSE
BoardOutlineClearance [OnCopper and Not InComponentClass('Logo') and not InComponentClass('FiducialMark') and not InRegion(1000,500,4000,800) and not InPoly] p3: gap=15 ignorepadtopadclearanceinfootprint=FALSE
Clearance Clearance_Keepouts [((IsTrack Or IsArc) And Not InPoly) And IsFree and IsKeepOut vs ((IsTrack Or IsArc) And Not InPoly) And IsFree and IsKeepOut] p1: gap=0 ignorepadtopadclearanceinfootprint=FALSE
Clearance Clearance_Poly [InPolygon] p2: gap=5.63 ignorepadtopadclearanceinfootprint=FALSE except(0: Arc-Hole Track-Hole SMDPad-Hole THPad-Hole Via-Hole Fill-Hole Poly-Hole Region-Hole Text-Hole)
Clearance [Not InComponentClass('FiducialMark')] p3: gap=5.63 ignorepadtopadclearanceinfootprint=TRUE except(0: Arc-Hole Track-Hole SMDPad-Hole THPad-Hole Via-Hole Fill-Hole Poly-Hole Region-Hole Text-Hole)
ComponentClearance ComponentClearance_MountingHoles_FiducialMarks [InComponentClass('Mounting Holes') vs InComponentClass('FiducialMark')] p1: gap=50 collisioncheckmode=3 verticalgap=10 showdistances=FALSE
ComponentClearance ComponentClearance_Shunt [InComponentClass('Header') vs InComponentClass('Shunt')] p2: gap=0 collisioncheckmode=3 verticalgap=0 showdistances=FALSE
ComponentClearance ComponentClearance_NetTie [IsNetTieComponent] p3: gap=0 collisioncheckmode=3 verticalgap=10 showdistances=FALSE
ComponentClearance ComponentClearance_Logo [InComponentClass('Logo')] p4: gap=50 collisioncheckmode=3 verticalgap=10 showdistances=FALSE
ComponentClearance ComponentClearance_ScrewToNut [(HasFootprint('NY PMS 440 0025 PH')) vs (HasFootprint('Keystone_1902C'))] p5: gap=5 collisioncheckmode=3 verticalgap=10 showdistances=FALSE
ComponentClearance ComponentClearance_MountingHoles_Bumpon [InComponentClass('Mounting Holes') vs HasFootprint('Bumpon_SJ5003Transparent')] p6: gap=0 collisioncheckmode=3 verticalgap=0 showdistances=FALSE
ComponentClearance ComponentClearance_MountingHoles [InComponentClass('Mounting Holes')] p7: gap=250 collisioncheckmode=3 verticalgap=100000 showdistances=FALSE
ComponentClearance ComponentClearance_SmallPassives [HasFootprint('0201*') or HasFootprint('0402*') or HasFootprint('0508') or HasFootprint('0603*') or HasFootprint('0612') or HasFootprint('0805*') or HasFootprint('0815*') or HasFootprint('0830*') or HasFootprint('1206*') or HasFootprint('1210*') or HasFootprint('1808*') or HasFootprint('1812*') or HasFootprint('1825*') or HasFootprint('2010*') or HasFootprint('2220*') or HasFootprint('2225*') or HasFootprint('2512*') or HasFootprint('2728*') or HasFootprint('3518*') vs HasFootprint('0201*') or HasFootprint('0402*') or HasFootprint('0508') or HasFootprint('0603*') or HasFootprint('0612') or HasFootprint('0805*') or HasFootprint('0815*') or HasFootprint('0830*') or HasFootprint('1206*') or HasFootprint('1210*') or HasFootprint('1808*') or HasFootprint('1812*') or HasFootprint('1825*') or HasFootprint('2010*') or HasFootprint('2220*') or HasFootprint('2225*') or HasFootprint('2512*') or HasFootprint('2728*') or HasFootprint('3518*')] p8: gap=14.96 collisioncheckmode=3 verticalgap=10 showdistances=FALSE
ComponentClearance ComponentClearance_THtoSMT [IsThruComponent vs IsSMTComponent] p9: gap=40 collisioncheckmode=3 verticalgap=30 showdistances=FALSE
ComponentClearance ComponentClearance_THtoTH [IsThruComponent vs IsThruComponent] p10: gap=30 collisioncheckmode=3 verticalgap=30 showdistances=FALSE
ComponentClearance ComponentClearance_Bumpon [HasFootprint('Keystone_1902C') vs HasFootprint('Bumpon_SJ5003Transparent')] p11: gap=0 collisioncheckmode=3 verticalgap=0 showdistances=FALSE
ComponentClearance [All] p12 off: gap=30 collisioncheckmode=3 verticalgap=10 showdistances=FALSE
DiffPairsRouting [All] p1: maxlimit=100 minlimit=10 mostfreqgap=10 toplayer_minwidth=15 toplayer_maxwidth=15 toplayer_prefwidth=15 midlayer1_minwidth=15 midlayer1_maxwidth=15 midlayer1_prefwidth=15 midlayer2_minwidth=15 midlayer2_maxwidth=15 midlayer2_prefwidth=15 midlayer3_minwidth=15 midlayer3_maxwidth=15 midlayer3_prefwidth=15 midlayer4_minwidth=15 midlayer4_maxwidth=15 midlayer4_prefwidth=15 midlayer5_minwidth=15 midlayer5_maxwidth=15 midlayer5_prefwidth=15 midlayer6_minwidth=15 midlayer6_maxwidth=15 midlayer6_prefwidth=15 bottomlayer_minwidth=15 bottomlayer_maxwidth=15 bottomlayer_prefwidth=15 maxuncoupledlength=1000
FabricationTestPointUsage TestPointUsage [All] p1: valid=2 allowmultiple=FALSE
FabricationTestpoint Testpoint [All] p1: side=3 testpointundercomponent=TRUE minsize=40 maxsize=100 preferedsize=60 minholesize=0 maxholesize=40 preferedholesize=32 testpointgrid=1 allowsidetop=TRUE allowsidebottom=TRUE usegrid=TRUE gridtolerance=0.01
FanoutControl Fanout_LCC [IsLCC] p1: bgadir=Out bgaviamode=Centered fanoutstyle=Auto fanoutdirection=Alternating viagrid=1 // Fanout_LCC (Default Rule)
FanoutControl Fanout_BGA [IsBGA] p2: bgadir=Out bgaviamode=Centered fanoutstyle=Auto fanoutdirection=Alternating viagrid=1 // Fanout_BGA (Default Rule)
FanoutControl Fanout_Default [All] p4: bgadir=Out bgaviamode=Centered fanoutstyle=Auto fanoutdirection=Alternating viagrid=1 // Fanout_Default (Default Rule)
FanoutControl Fanout_Small [(CompPinCount < 5)] p5: bgadir=Out bgaviamode=Centered fanoutstyle=Auto fanoutdirection=OutThenIn viagrid=1 // Fanout_Small (Default Rule)
HoleSize [All] p1: absolutevalues=TRUE maxlimit=251 minlimit=6 maxpercent=80.000 minpercent=20.000
HoleToHoleClearance [All] p1: gap=10 allowstackedmicrovias=FALSE
MinimumAnnularRing MinimumAnnularRing_ThermalPadVias [IsVia and InAnyComponent] p1: minimumring=5
MinimumAnnularRing [All] p2: minimumring=5
MinimumSolderMaskSliver MinimumSolderMaskSliver_Logo [InComponentClass('Logo') vs InComponentClass('Logo')] p1: minsoldermaskwidth=0.7
MinimumSolderMaskSliver [All] p2: minsoldermaskwidth=3.73
PlaneConnect [All] p1: planeconnectstyle=Relief reliefexpansion=10 reliefentries=4 reliefconductorwidth=10 reliefairgap=10
PolygonConnect PolygonDirectConnect [(IsNamedPolygon('TOP_LAYER_NETJ14_2_P107'))] p1: thpad.connectstyle=Relief thpad.reliefconductorwidth=10 thpad.reliefentries=4 thpad.polygonreliefangle="90 Angle" thpad.airgapwidth=10 smdpad.connectstyle=Direct smdpad.reliefconductorwidth=10 smdpad.reliefentries=4 smdpad.polygonreliefangle="90 Angle" smdpad.airgapwidth=10 via.connectstyle=Direct via.reliefconductorwidth=10 via.reliefentries=4 via.polygonreliefangle="90 Angle" via.airgapwidth=10
PolygonConnect [All] p2: thpad.connectstyle=Relief thpad.reliefconductorwidth=10 thpad.reliefentries=4 thpad.polygonreliefangle="90 Angle" thpad.airgapwidth=10 smdpad.connectstyle=Relief smdpad.reliefconductorwidth=10 smdpad.reliefentries=4 smdpad.polygonreliefangle="90 Angle" smdpad.airgapwidth=10 via.connectstyle=Direct via.reliefconductorwidth=10 via.reliefentries=4 via.polygonreliefangle="90 Angle" via.airgapwidth=10
RoutingLayers [All] p1: top layer_v5=TRUE mid layer 1_v5=TRUE mid layer 2_v5=TRUE mid layer 3_v5=FALSE mid layer 4_v5=FALSE mid layer 5_v5=FALSE mid layer 6_v5=FALSE bottom layer_v5=TRUE
RoutingVias ThermalPadVias [IsVia and InAnyComponent] p1: holewidth=7 width=15 viastyle="Through Hole" minholewidth=7 minwidth=15 maxholewidth=12.99 maxwidth=23.62
RoutingVias [All] p2: holewidth=7 width=15 viastyle="Through Hole" minholewidth=7 minwidth=15 maxholewidth=40 maxwidth=65
SilkToBoardRegionClearance [Not ((IsComment or IsDesignator) And (Hide <> 'False')) and not InRegion(1000,500,4000,800)] p1:
SilkToSilkClearance SilkToSilkClearance_Pb-FreeLogo [(HasFootprint('Pb-Free_Overlay_Medium') OR HasFootprint('Pb-Free_Overlay_Small')) vs (HasFootprint('Pb-Free_Overlay_Medium') OR HasFootprint('Pb-Free_Overlay_Small'))] p1: silktosilkclearance=0
SilkToSilkClearance [All] p2: silktosilkclearance=4
SilkToSolderMaskClearance SilkToComponentPadClearance [(IsPad or IsFill or IsRegion) and InAnycomponent] p1: minsilkscreentomaskgap=5 clearancetoexposedcopper=TRUE
SilkToSolderMaskClearance "Silk to Solder Mask Opening" [All] p2: minsilkscreentomaskgap=4 clearancetoexposedcopper=FALSE
SolderMaskExpansion [All] p1: expansion=1.97 istentingtop=FALSE
Width [All] p1: maxlimit=100 minlimit=6 preferedwidth=10 checkconnectedcopper=TRUE
13 further rules are at their usual default settings.

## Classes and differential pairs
component class Shunt: SH-J1 SH-J2 SH-J3 SH-J4
component class FabricationNote: ZZ4 ZZ5 ZZ6 ZZ7 ZZ8
component class TIDA-050061_Load: C19 C20 C21 C22 C23 C24 C25 J18 J19 J20 J21 J22 J23 J24 J25 Q1 R11 R12 R13 R14 R15 R16 R17 R18 R19 R20 R21 R22 R23 R24 R25 U4
component class TIDA-050061_Input_Cap: C26 C27 C28 C29 C30 C31 C32 C33 C34 C35 C36 C37 C38 C39 C40 C41 C42 C43 C44 C45 C46 C47 C48 C49 C50 C51 C52 C53 C54 C55 C56 C57 C58 C59 C60 C61 C62 C63 C64 C65 C66 C67 C68 C69 C70 C71 C72 C73 C74 C75 C76 C77 C78 C79 C80 C81 C82 J26 J27 J28 J29 J30 J31 J32 R26 R27 R28
component class Header: J3 J6 J10 J13 J16 J18 J28
component class TIDA-050061_LDO: C1 C2 C3 C4 C5 C6 C7 C8 C9 C10 C11 C12 C13 C14 C15 C16 C17 C18 J1 J2 J3 J4 J5 J6 J7 J8 J9 J10 J11 J12 J13 J14 J15 J16 J17 R1 R2 R3 R4 R5 R6 R7 R8 R9 R10 TP1 TP2 TP3 U1 U2 U3
component class TIDA-050061_Hardware: FID1 FID2 FID3 FID4 FID5 FID6 FID7 FID8 FID9 FID10 LOGO1 Logo2 Logo4 Logo5 MP1 MP2 SH-J1 SH-J2 SH-J3 SH-J4 ZZ1 ZZ2 ZZ3 ZZ4 ZZ5 ZZ6 ZZ7 ZZ8
component class FiducialMark: FID1 FID2 FID3 FID4 FID5 FID6 FID7 FID8 FID9 FID10
component class AssemblyNote: ZZ1 ZZ2 ZZ3

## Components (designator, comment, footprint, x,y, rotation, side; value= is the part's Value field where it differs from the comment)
C1 "20SEF560M" FP-20SEF560M_RADIAL-MFG 3030.84,893.33 r90 bottom value=560µF
C2 "GRM32ER7YA106KA12K" 1210_270 2969,-729.89 r0 top value=10uF
C3 "C0603C475K8PACTU" 0603 2592.86,1028.66 r0 top value=4.7uF
C4 "GRM21BZ71A226ME15L" 0805_HV 3051.27,1515.75 r90 top value=22uF
C5 "GRM21BZ71A226ME15L" 0805_HV 2971.1,1515.59 r90 top value=22uF
C6 "TPSC106M025R0500" 6032-28 2810.88,-972.12 r0 top value=10uF
C7 "GRM21BZ71A226ME15L" 0805_HV 2751.1,1344.04 r270 top value=22uF
C8 "TMK212B7225KG-TR" 0805_HV 2831.46,1344.6 r270 top value=2.2uF
C9 "GMC04X7R105K10NT" FP-GMC04X7R105K10NT_0402-IPC_A 2681.36,1311.12 r90 top value=1µF
C10 "GRM188Z71C475KE21D" 0603 2782.18,1384.04 r90 bottom value=4.7uF
C11 "GRM21BZ71A226ME15L" 0805_HV 2751.57,1114.21 r270 top value=22uF
C12 "TMK212B7225KG-TR" 0805_HV 2832.07,1113.21 r270 top value=2.2uF
C13 "GMC04X7R105K10NT" FP-GMC04X7R105K10NT_0402-IPC_A 2681.88,1033.54 r90 top value=1µF
C14 "GRM188Z71C475KE21D" 0603 2777.45,990.59 r270 bottom value=4.7uF
C15 "GRM21BZ71A226ME15L" 0805_HV 2764.65,835.2 r270 top value=22uF
C16 "TMK212B7225KG-TR" 0805_HV 2845.01,835.2 r270 top value=2.2uF
C17 "GMC04X7R105K10NT" FP-GMC04X7R105K10NT_0402-IPC_A 2705.87,788.4 r90 top value=1µF
C18 "GRM188Z71C475KE21D" 0603 2705.05,714 r0 bottom value=4.7uF
C19 "CL05A105KP5NNNC-R" 0805 3088.21,1742.85 r270 bottom value=1pF
C20 "TPSC106M025R0500" 6032-28 3088.41,3225.18 r0 top value=10uF
C21 "C1005X7R1H104K050BB" 0402 2899.21,1730.53 r270 top value=0.1uF
C22 "GMC31X7R106K50NT" FP-GMC31X7R106K50NT_1206-MFG 2729.47,1802.89 r90 top value=10µF
C23 "GMC31X7R106K50NT" FP-GMC31X7R106K50NT_1206-MFG 2823.96,1802.89 r90 top value=10µF
C24 "06031C102JAT2A" 0603 3065.12,1616.89 r0 bottom value=1000pF
C25 "06031C102JAT2A" 0603 3116.76,1525.1 r90 bottom value=1000pF
C26 "TPSC106M025R0500" 6032-28 481.02,2016.93 r270 top value=10uF
C27 "CGA4J1X7R1H475K125AC" FP-CGA4J1X7R1H475K125AC_0805-IPC_A 2270.15,1523.34 r0 top value=4.7µF
C28 "20SEF560M" FP-20SEF560M_RADIAL-MFG 633.37,1951.97 r90 bottom value=560µF
C29 "20SEF560M" FP-20SEF560M_RADIAL-MFG 1061.89,1950 r90 bottom value=560µF
C30 "20SEF560M" FP-20SEF560M_RADIAL-MFG 2268.18,1597.74 r0 bottom value=560µF
C31 "20SEF560M" FP-20SEF560M_RADIAL-MFG 2267.49,2026.29 r0 bottom value=560µF
C32 "CL32B226KAJNFNE" 1210_270M 2274.45,1722.56 r180 top value=22uF
C33 "CL32B226KAJNFNE" 1210_270M 2273.73,1904.76 r180 top value=22uF
C34 "C0805C105K4RACAUTO" 0805_HV 2269.45,1439.74 r180 top value=1uF
C35 "UMK105B7104MV-FR" 0402M 2269.45,1597.74 r180 top value=0.1uF
C36 "UMK105B7104MV-FR" 0402M 2269.45,2030.83 r180 top value=0.1uF
C37 "UMK105B7104MV-FR" 0402M 2274.45,1812.95 r180 top value=0.1uF
C38 "CGA4J1X7R1H475K125AC" FP-CGA4J1X7R1H475K125AC_0805-IPC_A 1135.26,1953.94 r90 top value=4.7µF
C39 "CL32B226KAJNFNE" 1210_270M 945.74,1950.91 r270 top value=22uF
C40 "CL32B226KAJNFNE" 1210_270M 762.39,1951.83 r270 top value=22uF
C41 "C0805C105K4RACAUTO" 0805_HV 1223.26,1950.91 r270 top value=1uF
C42 "UMK105B7104MV-FR" 0402M 855.23,1953.94 r270 top value=0.1uF
C43 "UMK105B7104MV-FR" 0402M 1061.89,1950 r270 top value=0.1uF
C44 "UMK105B7104MV-FR" 0402M 633.37,1951.97 r270 top value=0.1uF
C45 "TPSC106M025R0500" 6032-28 470.18,1032.76 r90 top value=10uF
C46 "CGA4J1X7R1H475K125AC" FP-CGA4J1X7R1H475K125AC_0805-IPC_A 1905.86,915.57 r90 top value=4.7µF
C47 "CGA4J1X7R1H475K125AC" FP-CGA4J1X7R1H475K125AC_0805-IPC_A 1912.67,1344.04 r270 top value=4.7µF
C48 "20SEF560M" FP-20SEF560M_RADIAL-MFG 1413.37,917.66 r90 bottom value=560µF
C49 "20SEF560M" FP-20SEF560M_RADIAL-MFG 1839.01,917.66 r90 bottom value=560µF
C50 "CL32B226KAJNFNE" 1210_270M 1533.21,918.18 r270 top value=22uF
C51 "CL32B226KAJNFNE" 1210_270M 1720.28,917.5 r270 top value=22uF
C52 "C0805C105K4RACAUTO" 0805_HV 1990.48,917.14 r270 top value=1uF
C53 "UMK105B7104MV-FR" 0402M 1839.01,918.54 r270 top value=0.1uF
C54 "UMK105B7104MV-FR" 0402M 1626.58,919.42 r270 top value=0.1uF
C55 "UMK105B7104MV-FR" 0402M 1413.37,917.65 r270 top value=0.1uF
C56 "20SEF560M" FP-20SEF560M_RADIAL-MFG 1839.01,1346.08 r270 bottom value=560µF
C57 "20SEF560M" FP-20SEF560M_RADIAL-MFG 1413.37,1344.92 r270 bottom value=560µF
C58 "CL32B226KAJNFNE" 1210_270M 1533.21,1347.99 r90 top value=22uF
C59 "CL32B226KAJNFNE" 1210_270M 1720.28,1348.28 r90 top value=22uF
C60 "C0805C105K4RACAUTO" 0805_HV 2003.37,1343.01 r90 top value=1uF
C61 "UMK105B7104MV-FR" 0402M 1626.58,1346.18 r90 top value=0.1uF
C62 "UMK105B7104MV-FR" 0402M 1839.01,1346.08 r90 top value=0.1uF
C63 "UMK105B7104MV-FR" 0402M 1411.4,1346.08 r90 top value=0.1uF
C64 "TPSC106M025R0500" 6032-28 480.8,277.08 r90 top value=10uF
C65 "CGA4J1X7R1H475K125AC" FP-CGA4J1X7R1H475K125AC_0805-IPC_A 2265.4,734.44 r0 top value=4.7µF
C66 "20SEF560M" FP-20SEF560M_RADIAL-MFG 1057.95,330 r270 bottom value=560µF
C67 "20SEF560M" FP-20SEF560M_RADIAL-MFG 630.9,330 r270 bottom value=560µF
C68 "20SEF560M" FP-20SEF560M_RADIAL-MFG 2268.69,663.01 r0 bottom value=560µF
C69 "20SEF560M" FP-20SEF560M_RADIAL-MFG 2268.69,231.05 r0 bottom value=560µF
C70 "CL32B226KAJNFNE" 1210_270M 2271.5,350.74 r180 top value=22uF
C71 "CL32B226KAJNFNE" 1210_270M 2269.23,537.75 r180 top value=22uF
C72 "C0805C105K4RACAUTO" 0805_HV 2266.45,824.98 r180 top value=1uF
C73 "UMK105B7104MV-FR" 0402M 2268.69,663.01 r180 top value=0.1uF
C74 "UMK105B7104MV-FR" 0402M 2270.66,229.08 r180 top value=0.1uF
C75 "UMK105B7104MV-FR" 0402M 2268.69,443.89 r180 top value=0.1uF
C76 "CGA4J1X7R1H475K125AC" FP-CGA4J1X7R1H475K125AC_0805-IPC_A 1130.8,328.03 r270 top value=4.7µF
C77 "CL32B226KAJNFNE" 1210_270M 941.81,328.03 r90 top value=22uF
C78 "CL32B226KAJNFNE" 1210_270M 760.58,330 r90 top value=22uF
C79 "C0805C105K4RACAUTO" 0805_HV 1222.51,328.03 r90 top value=1uF
C80 "UMK105B7104MV-FR" 0402M 628.93,328.03 r90 top value=0.1uF
C81 "UMK105B7104MV-FR" 0402M 851.27,328.03 r90 top value=0.1uF
C82 "UMK105B7104MV-FR" 0402M 1057.95,330 r90 top value=0.1uF
FID1 "Fiducial" Fiducial10-20 3900,3275 r90 bottom
FID2 "Fiducial" Fiducial10-20 3900,-1025 r90 bottom
FID3 "Fiducial" Fiducial10-20 2300,-1025 r90 bottom
FID4 "Fiducial" Fiducial10-20 40,50 r90 bottom
FID5 "Fiducial" Fiducial10-20 45,2220 r90 bottom
FID6 "Fiducial" Fiducial10-20 45,2220 r0 top
FID7 "Fiducial" Fiducial10-20 40,50 r0 top
FID8 "Fiducial" Fiducial10-20 3900,-1025 r0 top
FID9 "Fiducial" Fiducial10-20 3900,3275 r90 top
FID10 "Fiducial" Fiducial10-20 2300,-1025 r90 top
J1 "RF12-07H-T-00-50-G" FP-RF12-07H-T-00-50-G_CONN_MMCX-MFG 2777.45,1629.12 r0 top
J2 "571-0500" 571-0500 2599.01,-687.94 r90 bottom
J3 "61300311121" WURTH_61300311121 2488.97,2331.8 r180 top
J4 "RF2-04A-T-00-50-G" FP-RF2-04A-T-00-50-G_CONN_RF_7MM00_7MM00-MFG 2894.74,527.1 r0 top
J5 "RF12-07H-T-00-50-G" FP-RF12-07H-T-00-50-G_CONN_MMCX-MFG 2566.63,1641.34 r0 top
J6 "TSW-102-07-G-D" TSW-102-07-G-D 2967.78,-465.32 r270 top
J7 "RF2-04A-T-00-50-G" FP-RF2-04A-T-00-50-G_CONN_RF_7MM00_7MM00-MFG 2670.37,2065.11 r0 top
J8 "JMP-36-30X40SMT" JMP-36-30X40SMT 3039.92,-885.32 r180 top
J9 "571-0100" 571-0100 3349.01,-687.94 r90 bottom
J10 "61300311121" WURTH_61300311121 2491.25,2606.66 r180 top
J11 "691137710002" FP-691137710002_HDR2-MFG 3777.3,2336.86 r90 top
J12 "RF2-04A-T-00-50-G" FP-RF2-04A-T-00-50-G_CONN_RF_7MM00_7MM00-MFG 2451.7,3159.79 r0 top
J13 "61300311121" WURTH_61300311121 2298.69,-351.13 r90 top
J14 "JMP-36-30X40SMT" JMP-36-30X40SMT 2394.37,2460 r180 bottom
J15 "JMP-36-30X40SMT" JMP-36-30X40SMT 2390.69,2702.4 r180 bottom
J16 "61300311121" WURTH_61300311121 2488.97,2873.82 r180 top
J17 "JMP-36-30X40SMT" JMP-36-30X40SMT 2390.19,2767.07 r180 bottom
J18 "PBC02SAAN" Sullins_PBC02SAAN 3143.61,1263.87 r90 top
J19 "RF12-07H-T-00-50-G" FP-RF12-07H-T-00-50-G_CONN_MMCX-MFG 3155.53,1980.87 r0 top
J20 "JMP-36-30X40SMT" JMP-36-30X40SMT 3208.55,1533.6 r90 bottom
J21 "VDD" 571-0500 2843.34,2952.07 r270 bottom
J22 "RF2-04A-T-00-50-G" FP-RF2-04A-T-00-50-G_CONN_RF_7MM00_7MM00-MFG 3226.99,2862.07 r0 top
J23 "RF12-07H-T-00-50-G" FP-RF12-07H-T-00-50-G_CONN_MMCX-MFG 2969.42,1902.61 r0 top
J24 "JMP-36-30X40SMT" JMP-36-30X40SMT 3298.33,3225.18 r180 top
J25 "GND" 571-0100 3593.34,2952.07 r270 bottom
J26 "JMP-36-30X40SMT" JMP-36-30X40SMT 541.39,1771.35 r90 top
J27 "571-0500" 571-0500 385.59,755.21 r0 bottom
J28 "TSW-102-07-G-D" TSW-102-07-G-D 2171.5,994.16 r180 top
J29 "JMP-36-30X40SMT" JMP-36-30X40SMT 567.02,1259.81 r270 top
J30 "691137710002" FP-691137710002_HDR2-MFG 169.84,1123.82 r270 top
J31 "571-0100" 571-0100 385.59,1505.21 r0 bottom
J32 "JMP-36-30X40SMT" JMP-36-30X40SMT 541.39,532.37 r270 top
LOGO1 "CAUTION HOT SURFACE" IEC_HotSurface_Small 2331.61,1251.31 r90 top
Logo2 "CE Mark" CE_Mark_5mm 2361.27,-795.32 r270 top
Logo4 "FCC disclaimer" FCC_disclaimer 3893.37,2515.65 r270 bottom
Logo5 "WEEE logo" WEEE_Minimum 189.31,1961.81 r0 top
MP1 "19.05MM-6.35MM-25-8810" FP-19.05MM-6.35MM-25-8810_THERMAL_PAD-MFG 2616.63,1132.4 r90 bottom
MP2 "V5618B" FP-V5618B_HEATSINK-MFG 2616.63,1132.4 r90 bottom
Q1 "ISK024NE2LM5AULA1" FP-ISK024NE2LM5AULA1_VSON6-MFG 3168.55,1650.99 r270 top
R1 "ULR1S-R0025FT2" FP-ULR1S-R0025FT2_1206-MFG 2814.46,1461.82 r0 top value=2.5m
R2 "CRCW0402100KFKEDC" FP-CRCW0402100KFKEDC_0402-IPC_A 2643.22,1520.53 r180 top value=100k
R3 "ERJ-6BQF1R0V" 0805_HV 3043.37,-985.32 r180 top value=1.00
R4 "ULR1S-R0025FT2" FP-ULR1S-R0025FT2_1206-MFG 2817.56,1223.9 r0 top value=2.5m
R5 "CRCW0402100KFKEDC" FP-CRCW0402100KFKEDC_0402-IPC_A 2642.26,1251.59 r180 top value=100k
R6 "CRCW04024K99FKED" 0402 2613.05,696.48 r90 top value=4.99k
R7 "ULR1S-R0025FT2" FP-ULR1S-R0025FT2_1206-MFG 2815.9,950.79 r0 top value=2.5m
R8 "CRCW0402100KFKEDC" FP-CRCW0402100KFKEDC_0402-IPC_A 2639.31,969.37 r180 top value=100k
R9 "CRCW120649R9FKEAHP" FP-CRCW120649R9FKEAHP_1206-MFG 2374.26,2957.99 r0 bottom value=49.9
R10 "CRCW04024K99FKED" 0402 2604.63,1318.16 r0 top value=4.99k
R11 "WSL12065L000FEA18" 1206 3693.37,-375.32 r90 bottom value=0.005
R12 "ERJ-B2CFR05V" 0612 3150.31,1424.57 r180 top value=0.05
R13 "RC1210FR-07154RL" 1210 3731.52,1801.6 r90 top value=154
R14 "RC1210FR-07154RL" 1210 3604.67,1801.6 r90 top value=154
R15 "RC1210FR-07154RL" 1210 3476.23,1801.6 r90 top value=154
R16 "RC1210FR-07154RL" 1210 3348.45,1801.6 r90 top value=154
R17 "RC1210FR-07154RL" 1210 3221.52,1801.55 r90 top value=154
R18 "ERJ-6GEY0R00V" 0805_HV 3208.55,1752.19 r0 bottom value=0
R19 "RC0603FR-0720KL" 0603 3056.72,1759.68 r0 top value=20.0k
R20 "RC0603FR-0720KL" 0603 3056.72,1699.68 r0 top value=20.0k
R21 "ERJ-6ENF1001V" 0805_HV 3170.32,1549.85 r0 top value=1.00k
R22 "RMCF0603ZT0R00" 0603 3019.42,1710.91 r90 bottom value=0
R23 "RMCF0603ZT0R00" 0603 3173.55,1428.35 r0 bottom value=0
R24 "ERJ-6BQF1R0V" 0805_HV 3341.64,3122.07 r180 top value=1.00
R25 "CRCW120649R9FKEAHP" FP-CRCW120649R9FKEAHP_1206-MFG 3145.58,3082.07 r0 top value=49.9
R26 "ERJ-6BQF1R0V" 0805_HV 443.89,1774.35 r90 top value=1.00
R27 "ERJ-6BQF1R0V" 0805_HV 470.18,1265.56 r270 top value=1.00
R28 "ERJ-6BQF1R0V" 0805_HV 443.89,539.96 r270 top value=1.00
SH-J1 "SNT-100-BK-G" SNT-100-BK-G 2438.97,2873.82 r180 top value=1x2
SH-J2 "SNT-100-BK-G" SNT-100-BK-G 2438.97,2606.66 r180 top value=1x2
SH-J3 "SNT-100-BK-G" SNT-100-BK-G 2437.86,2331.8 r180 top value=1x2
SH-J4 "SNT-100-BK-G" SNT-100-BK-G 2295.98,-301.13 r90 top value=1x2
TP1 "5016" Testpoint_Keystone_Compact 3759.01,-476.76 r0 top
TP2 "5016" Testpoint_Keystone_Compact 3759.01,-656.76 r0 top
TP3 "5016" Testpoint_Keystone_Compact 3759.01,-839.95 r0 top
U1 "TPS7A5701RTET" RTE0016J-OV-MFG 2610.88,1420.16 r0 top
U2 "TPS7A5701RTET" RTE0016J-OV-MFG 2612.73,1152.08 r0 top
U3 "TPS7A5701RTET" RTE0016J-OV-MFG 2610.88,869.27 r0 top
U4 "LMG1020YFFR" YFF0006AEAE 2961.33,1721.4 r0 top
ZZ1 "These assemblies are ESD sensitive, ESD precautions shall be observed." AssemblyNote -2155.4,6210.94 r0 top
ZZ2 "These assemblies must be clean and free from flux and all contaminants. Use of no clean flux is not acceptable." AssemblyNote -2155.4,6122.39 r0 top
ZZ3 "These assemblies must comply with workmanship standards IPC-A-610 Class 2, unless otherwise specified." AssemblyNote -2155.4,6033.83 r0 top
ZZ4 "The slot dimensions shall be as shown in the figure below." AssemblyNote -2156.88,5941.03 r0 top
ZZ5 "There shall be two silkscreen colors on the top side of the PCB (BLACK and WHITE)." AssemblyNote -2156.88,5851.03 r0 top
ZZ6 "The OVERLAY layer shall use BLACK silkscreen." AssemblyNote -2156.88,5761.03 r0 top
ZZ7 "The MECHANICAL 20 and MECHANICAL 25 layers shall use WHITE silkscreen." AssemblyNote -2156.88,5671.03 r0 top
ZZ8 "Any component substitutions by the assembly house shall be in compliance with the latest RoHS and REACH directives." AssemblyNote -2160,5580 r0 top

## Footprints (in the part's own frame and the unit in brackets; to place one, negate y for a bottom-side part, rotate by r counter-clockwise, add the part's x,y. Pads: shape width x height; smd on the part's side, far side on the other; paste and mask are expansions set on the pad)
0402 [mm] "0402 from SM-752 data"
  rect 0.8x0.6 smd: 1(-0.6,0) 2(0.6,0)
  silkscreen extent -1.22,-0.52 1.22,0.52, body extent -0.55,-0.3 0.55,0.3, height 0.6
0402M [mm] "0402 from SM-752 data"
  rect 1x0.7 smd: 1(-0.7,0) 2(0.7,0)
  silkscreen extent -1.5,-0.64 1.51,0.65, body extent -0.55,-0.3 0.55,0.3, height 0.6
571-0100 [mm] "Deltron Emcon recommended land pattern 2003-10-13"
  rect 2.3x2.3 hole 1.8: 1(-7.65,0)
  round 2.3 hole 1.8: 2(7.65,0)
  silkscreen extent -9.74,-5.47 11.09,4.88, body extent -12.28,-5.47 11.09,4.88, height 12.41
571-0500 [mm] "Deltron Emcon recommended land pattern 2003-10-13"
  rect 2.3x2.3 hole 1.8: 1(-7.65,0)
  round 2.3 hole 1.8: 2(7.65,0)
  silkscreen extent -9.74,-5.47 11.09,4.88, body extent -12.28,-5.47 11.09,4.88, height 12.41
0603 [mm] "0603 from SM-752 data"
  rect 1x0.95 smd: 1(-0.8,0) 2(0.8,0)
  body extent -0.87,-0.47 0.87,0.47, height 1
0612 [mm] "Panasonic recommended land pattern, fb97d03ed01.pdf dated April 2008"
  rect 0.95x3.2 smd: 1(-0.775,0) 2(0.775,0)
  silkscreen extent -1.1,-1.9 1.1,1.9, body extent -0.9,-1.7 0.9,1.7, height 0.85
0805 [mm] "0805 from SM-752 data"
  rect 1.3x1.5 smd: 1(-0.85,0) 2(0.85,0)
  silkscreen extent -1.72,-0.97 1.72,0.97, body extent -1.1,-0.72 1.1,0.72, height 1.45
0805_HV [mil] "0805 with 30mil clearance between pads"
  rect 50x63 smd: 1(-40,0) 2(40,0)
  silkscreen extent -74,-40 74,40, body extent -43,-29 43,29, height 57
1206 [mm] "1206 from SM-752 data"
  rect 1.3x1.85 smd: 1(-1.45,0) 2(1.45,0)
  body extent -1.7,-0.9 1.7,0.9, height 1.35
1210 [mm] "1210 from SM-752 data"
  rect 1.3x2.7 smd: 1(-1.45,0) 2(1.45,0)
  silkscreen extent -2.32,-1.57 2.32,1.57, body extent -1.7,-1.35 1.7,1.35, height 1.35
1210_270 [mm] "1210"
  rect 1.3x2.7 smd: 1(-1.45,0) 2(1.45,0)
  silkscreen extent -2.32,-1.57 2.32,1.57, body extent -1.7,-1.35 1.7,1.35, height 2.7
1210_270M [mm] "1210"
  rect 1.5x2.8 smd: 1(-1.55,0) 2(1.55,0)
  silkscreen extent -2.75,-1.85 2.75,1.85, body extent -1.7,-1.35 1.7,1.35, height 2.7
6032-28 [mm] "Medium Density IPC based on Vishay Sprague 293D datasheet."
  rect 2.55x2.3 smd: 1(-2.375,0) 2(2.375,0)
  silkscreen extent -3.96,-1.75 3.2,1.82, body extent -3.15,-1.75 3.15,1.75, height 2.8
AssemblyNote [mil] "Assembly Note"
CE_Mark_5mm [mil] "Minimum text height for CE Mark"
  silkscreen extent -138,-98 138,98
FCC_disclaimer [mil]
Fiducial10-20 [mm]
  round 1 smd mask+0.5: 1(0,0)
  Top Layer keep-out circle w1.178: c0,0 r0.5
FP-19.05MM-6.35MM-25-8810_THERMAL_PAD-MFG [mil]
  body extent -375,-125 375,125, height 10
FP-20SEF560M_RADIAL-MFG [mm]
  rrect8% 1.3x1.3 hole 0.8 paste-1000 mask+0: 1(-2.5,0)
  round 1.3 hole 0.8 paste-1000 mask+0: 2(2.5,0)
  silkscreen extent -5.25,-5.25 5.25,5.25, body extent -5,-5 5,5, height 13
FP-691137710002_HDR2-MFG [mm]
  rrect5% 2x2 hole 1.3 paste-1000 mask+0: 1(-2.5,0.25)
  round 2 hole 1.3 paste-1000 mask+0: 2(2.5,0.25)
  silkscreen extent -5.05,-3.8 5.05,3.8, body extent -5.15,-3.9 5.15,3.9, height 0.25
FP-CGA4J1X7R1H475K125AC_0805-IPC_A [mm]
  rrect10% 0.956x1.556 smd paste+0 mask+0: 1(-1.175,0) 2(1.175,0)
  silkscreen extent -0.4,-0.78 0.4,0.78, body extent -2.15,-1.28 2.15,1.28, height 0.25
FP-CRCW120649R9FKEAHP_1206-MFG [mm]
  rrect10% 1.05x1.8 smd paste+0 mask+0: 1(-1.275,0) 2(1.275,0)
  silkscreen extent -0.38,-0.87 0.38,0.87, body extent -1.55,-0.8 1.55,0.8, height 0.65
FP-CRCW0402100KFKEDC_0402-IPC_A [mil]
  rrect15% 29.91x26.48 smd paste+0 mask+0: 1(-18.75,0) 2(18.75,0)
  body extent -42,-21 42,21, height 10
FP-GMC04X7R105K10NT_0402-IPC_A [mil]
  rrect15% 28.13x26.48 smd paste+0 mask+0: 1(-18.86,0) 2(18.86,0)
  body extent -41,-21 41,21, height 10
FP-GMC31X7R106K50NT_1206-MFG [mil]
  rrect10% 40x65 smd paste+0 mask+0: 1(-60,0) 2(60,0)
  silkscreen extent -25,-35 25,35, body extent -84,-39 84,39, height 10
FP-ISK024NE2LM5AULA1_VSON6-MFG [mm]
  rrect33% 0.5x0.3 smd paste-1000 mask+0: 1(-1,0.65) 2(-1,0) 3(-1,-0.65) 4(1,-0.65) 5(1,0) 6(1,0.65)
  rrect33% 1x0.3 smd paste-1000 mask+0: 4(0.075,-0.735)
  rrect10% 1.2x1 smd paste-1000 mask+0: 7(0,0.3)
  silkscreen extent -1.05,-1.3 1.05,1.85, body extent -1.35,-1.15 1.35,1.15, height 0.25
FP-RF2-04A-T-00-50-G_CONN_RF_7MM00_7MM00-MFG [mm]
  rrect4% 2.3x2.3 hole 1.5 paste-1000 mask+0: 1(0,0)
  round 2.45 hole 1.6 paste-1000 mask+0: 2(-2.55,2.55) 3(2.55,2.55) 4(-2.55,-2.55) 5(2.55,-2.55)
  silkscreen extent -4.42,-3.7 3.7,3.7, body extent -3.88,-3.88 3.88,3.88, height 0.25
FP-RF12-07H-T-00-50-G_CONN_MMCX-MFG [mm]
  rrect8% 1.3x1.3 hole 0.8 paste-1000 mask+0: 1(0,0)
  round 1.3 hole 0.8 paste-1000 mask+0: 2(-1.27,1.27) 3(1.27,1.27) 4(-1.27,-1.27) 5(1.27,-1.27)
  silkscreen extent -2.67,-1.94 1.94,1.94, body extent -2.04,-2.04 2.04,2.04, height 0.25
FP-ULR1S-R0025FT2_1206-MFG [mm]
  rrect10% 1.05x1.9 smd paste+0 mask+0: 1(-1.3,0) 2(1.3,0)
  body extent -1.92,-1.05 1.92,1.05, height 0.25
FP-V5618B_HEATSINK-MFG [mil]
  body extent -374,-124 374,124, height 189
IEC_HotSurface_Small [mil]
  silkscreen extent -107,-93 107,92
JMP-36-30X40SMT [mil] "from PADS library"
  rect 30x40 smd mask+3: 1(-18,0) 2(18,0)
RTE0016J-OV-MFG [mm]
  round 0.252 smd paste-1000 mask+0: 1(-1.475,0.75) 2(-1.475,0.25) 3(-1.76,-0.25) 4(-1.76,-0.75) 5(-0.75,-1.475) 6(-0.25,-1.475) 7(0.25,-1.76) 8(0.75,-1.76) 9(1.475,-0.75) 10(1.475,-0.25) 11(1.75,0.25) 12(1.75,0.75) 13(0.75,1.475) 14(0.25,1.475) 15(-0.25,1.75) 16(-0.75,1.75)
  rrect6% 1.7x1.7 smd paste-1000 mask+0: 17(0,0)
  Top Layer region: -1.9,0.89 -1.19,0.89 -1.136,0.879 -1.091,0.849 -1.061,0.804 -1.05,0.75 -1.05,0.75 -1.061,0.696 -1.091,0.651 -1.136,0.621 -1.19,0.61 -1.19,0.61 -1.9,0.61
  Top Layer region: -1.9,0.39 -1.19,0.39 -1.136,0.379 -1.091,0.349 -1.061,0.304 -1.05,0.25 -1.05,0.25 -1.061,0.196 -1.091,0.151 -1.136,0.121 -1.19,0.11 -1.19,0.11 -1.9,0.11
  Top Layer region: -1.9,-0.11 -1.19,-0.11 -1.136,-0.121 -1.091,-0.151 -1.061,-0.196 -1.05,-0.25 -1.05,-0.25 -1.061,-0.304 -1.091,-0.349 -1.136,-0.379 -1.19,-0.39 -1.19,-0.39 -1.9,-0.39
  Top Layer region: -1.9,-0.61 -1.19,-0.61 -1.136,-0.621 -1.091,-0.651 -1.061,-0.696 -1.05,-0.75 -1.05,-0.75 -1.061,-0.804 -1.091,-0.849 -1.136,-0.879 -1.19,-0.89 -1.19,-0.89 -1.9,-0.89
  Top Layer region: -0.89,-1.9 -0.89,-1.19 -0.879,-1.136 -0.849,-1.091 -0.804,-1.061 -0.75,-1.05 -0.75,-1.05 -0.696,-1.061 -0.651,-1.091 -0.621,-1.136 -0.61,-1.19 -0.61,-1.19 -0.61,-1.9
  Top Layer region: -0.39,-1.9 -0.39,-1.19 -0.379,-1.136 -0.349,-1.091 -0.304,-1.061 -0.25,-1.05 -0.25,-1.05 -0.196,-1.061 -0.151,-1.091 -0.121,-1.136 -0.11,-1.19 -0.11,-1.19 -0.11,-1.9
  Top Layer region: 0.11,-1.9 0.11,-1.19 0.121,-1.136 0.151,-1.091 0.196,-1.061 0.25,-1.05 0.25,-1.05 0.304,-1.061 0.349,-1.091 0.379,-1.136 0.39,-1.19 0.39,-1.19 0.39,-1.9
  Top Layer region: 0.61,-1.9 0.61,-1.19 0.621,-1.136 0.651,-1.091 0.696,-1.061 0.75,-1.05 0.75,-1.05 0.804,-1.061 0.849,-1.091 0.879,-1.136 0.89,-1.19 0.89,-1.19 0.89,-1.9
  Top Layer region: 1.9,-0.89 1.19,-0.89 1.136,-0.879 1.091,-0.849 1.061,-0.804 1.05,-0.75 1.05,-0.75 1.061,-0.696 1.091,-0.651 1.136,-0.621 1.19,-0.61 1.19,-0.61 1.9,-0.61
  Top Layer region: 1.9,-0.39 1.19,-0.39 1.136,-0.379 1.091,-0.349 1.061,-0.304 1.05,-0.25 1.05,-0.25 1.061,-0.196 1.091,-0.151 1.136,-0.121 1.19,-0.11 1.19,-0.11 1.9,-0.11
  Top Layer region: 1.9,0.11 1.19,0.11 1.136,0.121 1.091,0.151 1.061,0.196 1.05,0.25 1.05,0.25 1.061,0.304 1.091,0.349 1.136,0.379 1.19,0.39 1.19,0.39 1.9,0.39
  Top Layer region: 1.9,0.61 1.19,0.61 1.136,0.621 1.091,0.651 1.061,0.696 1.05,0.75 1.05,0.75 1.061,0.804 1.091,0.849 1.136,0.879 1.19,0.89 1.19,0.89 1.9,0.89
  Top Layer region: 0.89,1.9 0.89,1.19 0.879,1.136 0.849,1.091 0.804,1.061 0.75,1.05 0.75,1.05 0.696,1.061 0.651,1.091 0.621,1.136 0.61,1.19 0.61,1.19 0.61,1.9
  Top Layer region: 0.39,1.9 0.39,1.19 0.379,1.136 0.349,1.091 0.304,1.061 0.25,1.05 0.25,1.05 0.196,1.061 0.151,1.091 0.121,1.136 0.11,1.19 0.11,1.19 0.11,1.9
  Top Layer region: -0.11,1.9 -0.11,1.19 -0.121,1.136 -0.151,1.091 -0.196,1.061 -0.25,1.05 -0.25,1.05 -0.304,1.061 -0.349,1.091 -0.379,1.136 -0.39,1.19 -0.39,1.19 -0.39,1.9
  Top Layer region: -0.61,1.9 -0.61,1.19 -0.621,1.136 -0.651,1.091 -0.696,1.061 -0.75,1.05 -0.75,1.05 -0.804,1.061 -0.849,1.091 -0.879,1.136 -0.89,1.19 -0.89,1.19 -0.89,1.9
  body extent -1.5,-1.5 1.5,1.5, height 0.8
SNT-100-BK-G [mil] "Samtec STEP model"
  round 1 on Mech3: 0(0,0)
  body extent -100,-50 100,50, height 344
Sullins_PBC02SAAN [mm] "Sullins 100mil, 1x2, 230 mil above insulator"
  rect 1.65x1.65 hole 1.016: 1(0,1.27)
  round 1.65 hole 1.016: 2(0,-1.27)
  silkscreen extent -1.37,-2.54 1.27,3.1, body extent -1.27,-2.54 1.27,2.54, height 8.38
Testpoint_Keystone_Compact [mil] "Compact SMT test point"
  rect 185x135 smd: 1(0,0)
  silkscreen extent -110,-80 110,80, body extent -75,-56 75,56, height 91
TSW-102-07-G-D [mm] "Samtec 100mil, 2x2, 230 mil above insulator"
  rrect6% 1.65x1.65 hole 1.016: 1(-1.27,-1.27)
  round 1.65 hole 1.016: 2(-1.27,1.27) 3(1.27,-1.27) 4(1.27,1.27)
  silkscreen extent -3.56,-2.54 2.54,2.54, body extent -2.54,-2.54 2.54,2.54, height 8.38
WEEE_Minimum [mil] "WEEElie bin"
  silkscreen extent -95,-172 99,104
WURTH_61300311121 [mm] "Header, 2.54mm, 3x1, TH"
  rrect50% 1.65x1.65 hole 1.15: 1(-2.54,0)
  round 1.65 hole 1.15: 2(0,0) 3(2.54,0)
  body extent -3.81,-1.27 3.81,1.27, height 8.54
YFF0006AEAE [mm] "DSBGA-6"
  round 0.23 smd paste-0.13 mask+0.038: A1(-0.2,0.4) A2(0.2,0.4) B1(-0.2,0) B2(0.2,0) C1(-0.2,-0.4) C2(0.2,-0.4)
  body extent -0.45,-0.65 0.45,0.65, height 0.63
